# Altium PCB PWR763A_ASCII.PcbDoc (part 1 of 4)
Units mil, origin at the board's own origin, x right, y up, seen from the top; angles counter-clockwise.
Board outline 5000 x 7000 mil, 4 copper layers (Top Layer, Signal Layer 1, Signal Layer 2, Bottom Layer), stack 61.2 mil thick; 559 components, 281 nets, 1477 pads, 685 vias.
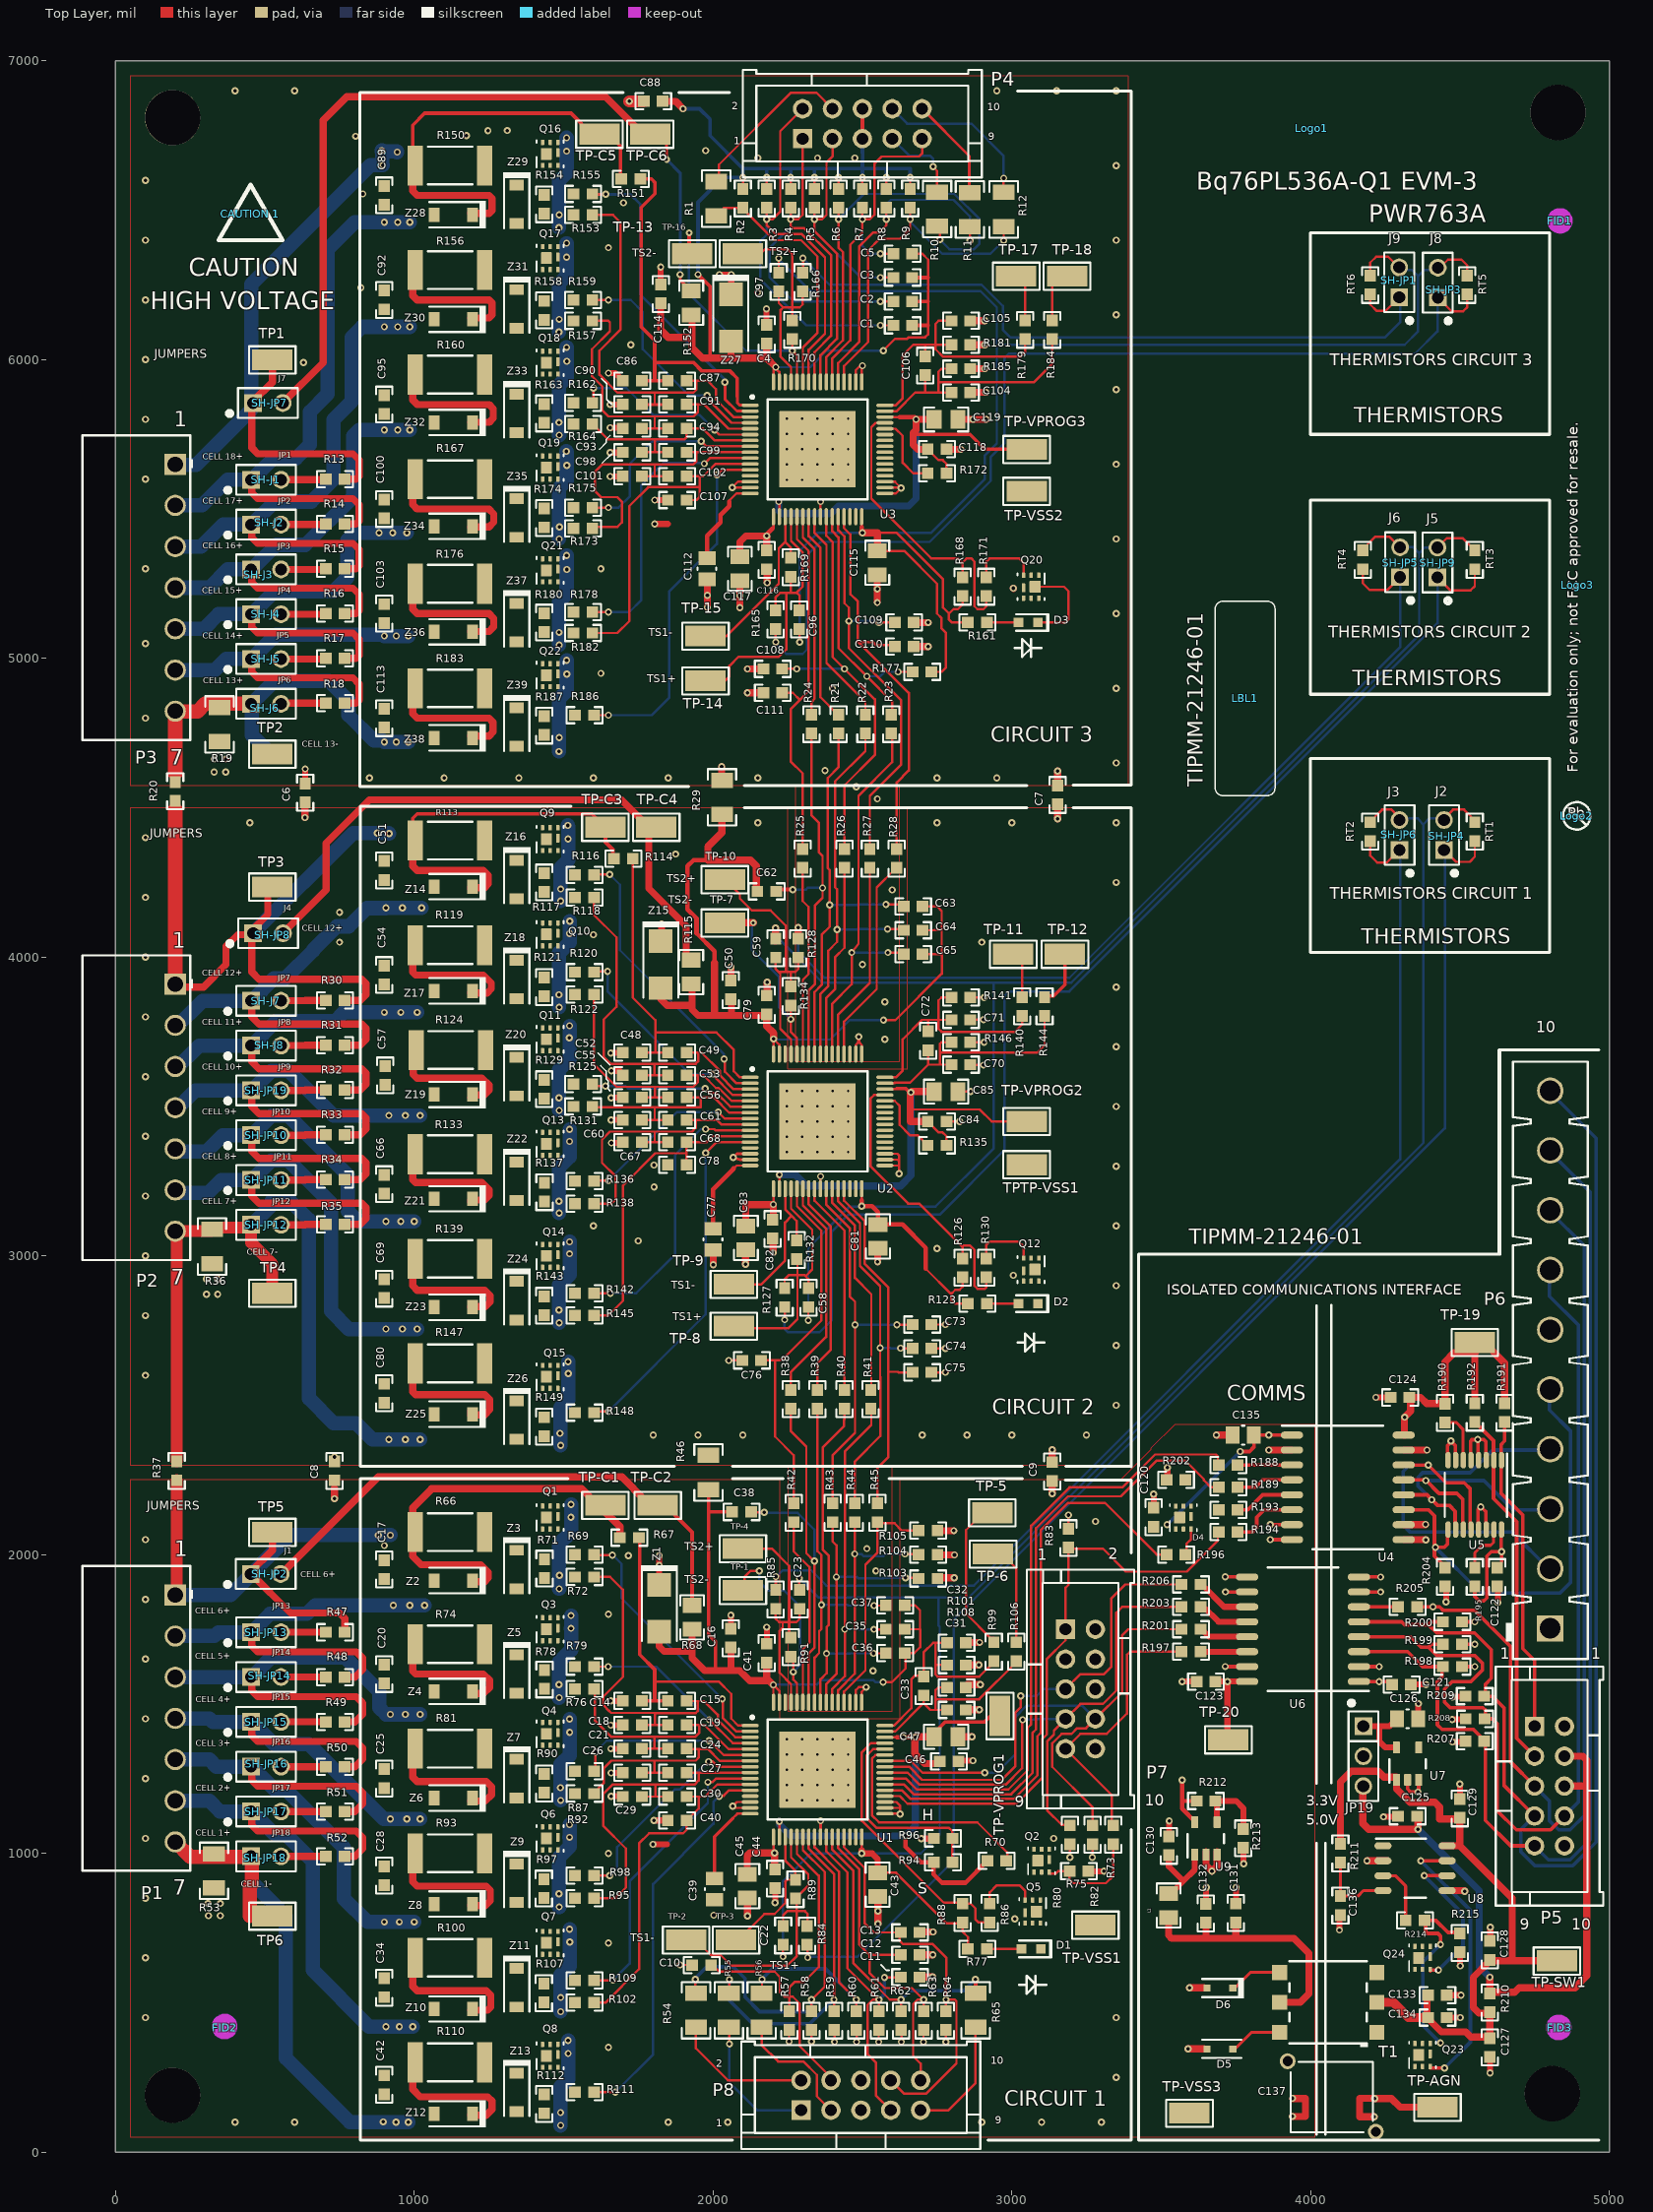
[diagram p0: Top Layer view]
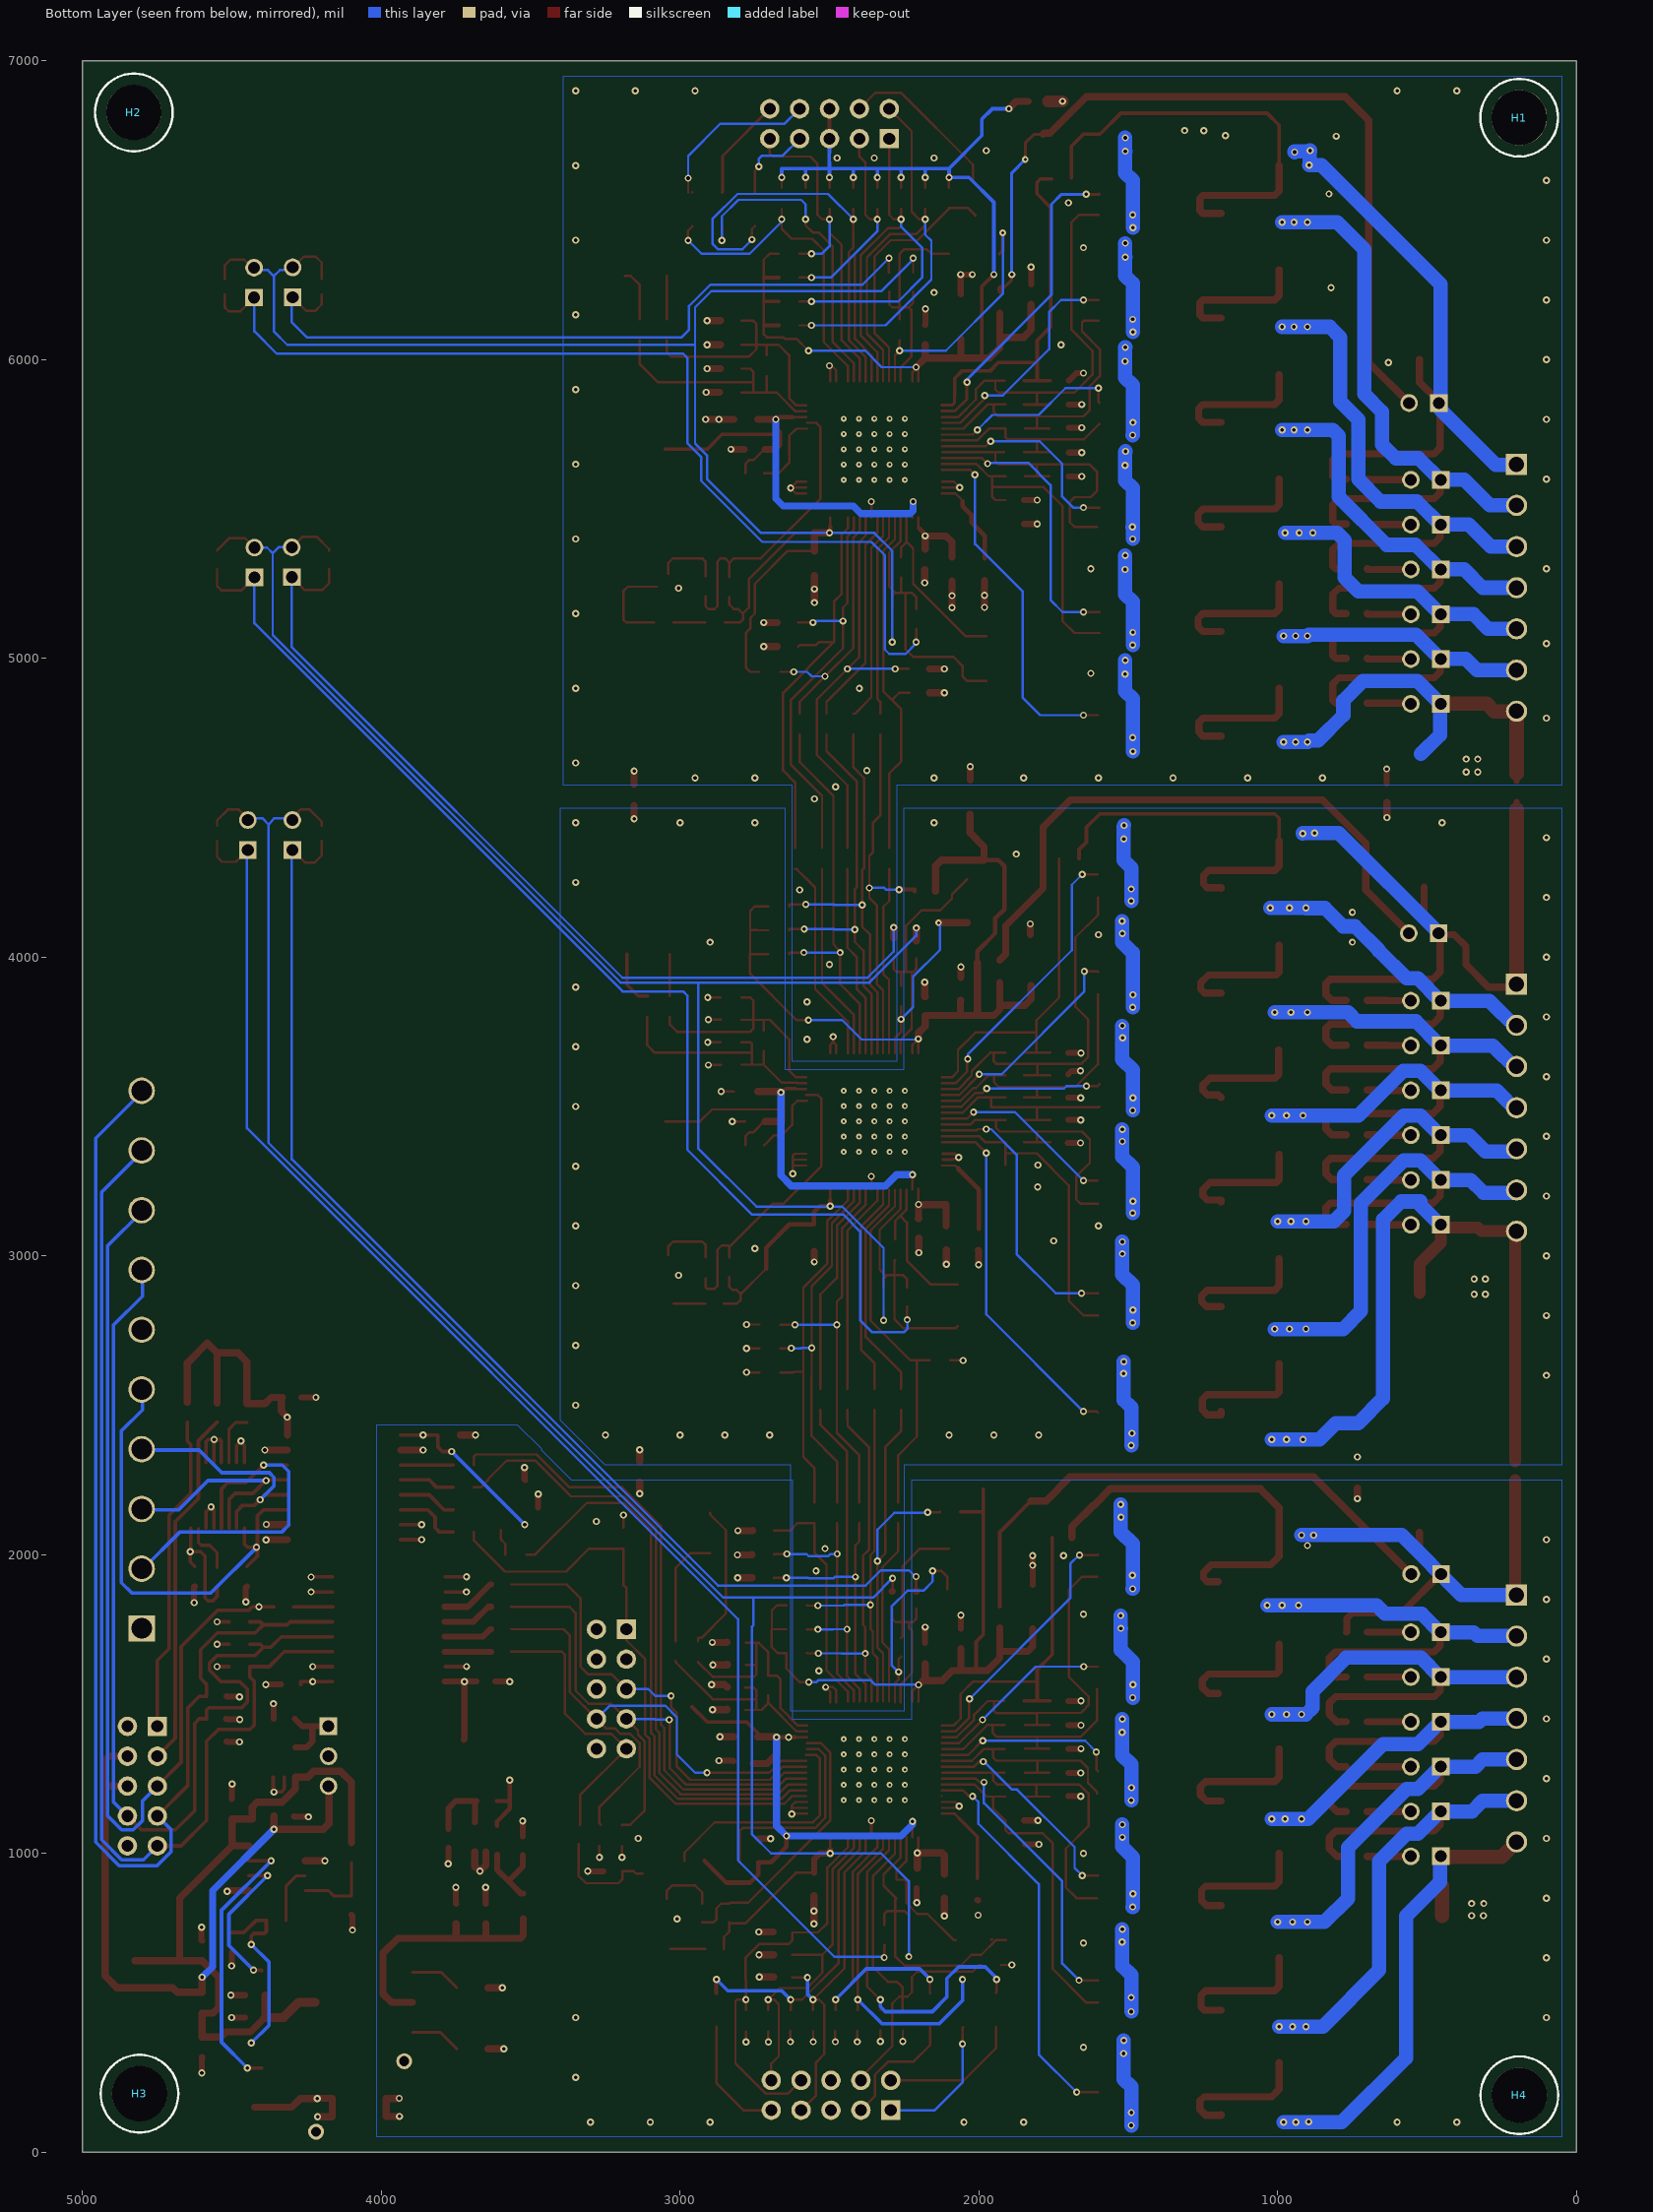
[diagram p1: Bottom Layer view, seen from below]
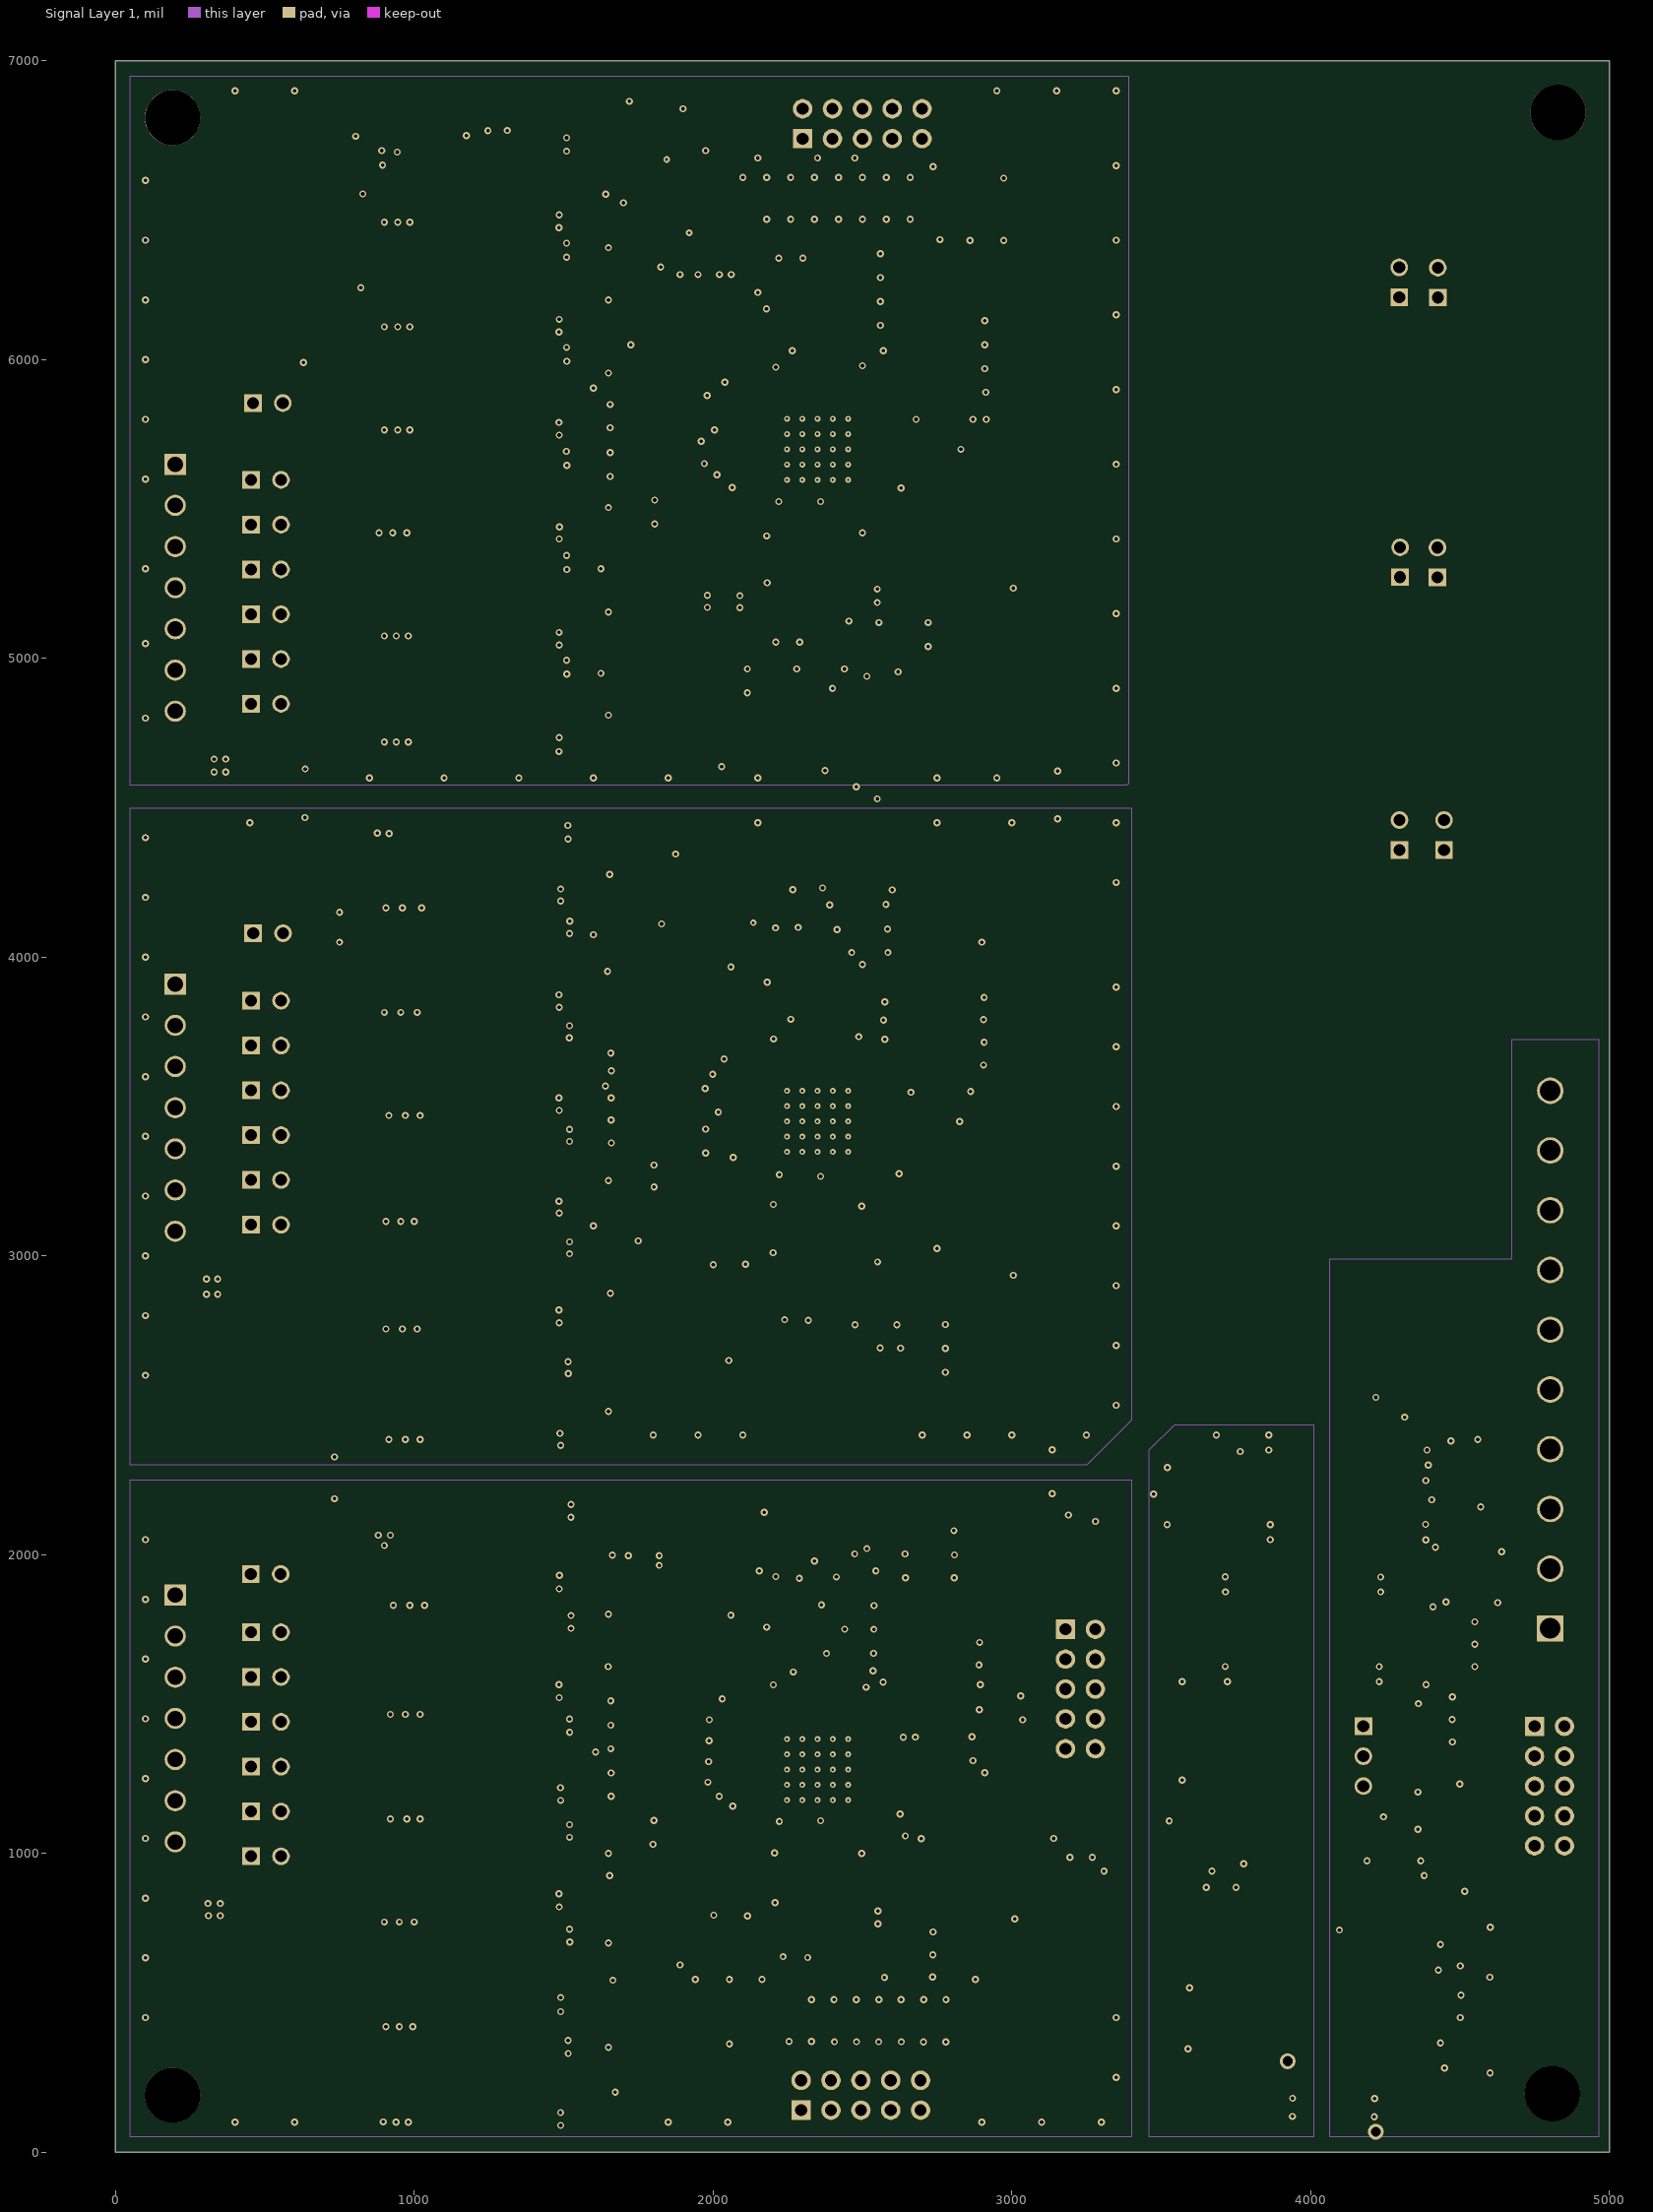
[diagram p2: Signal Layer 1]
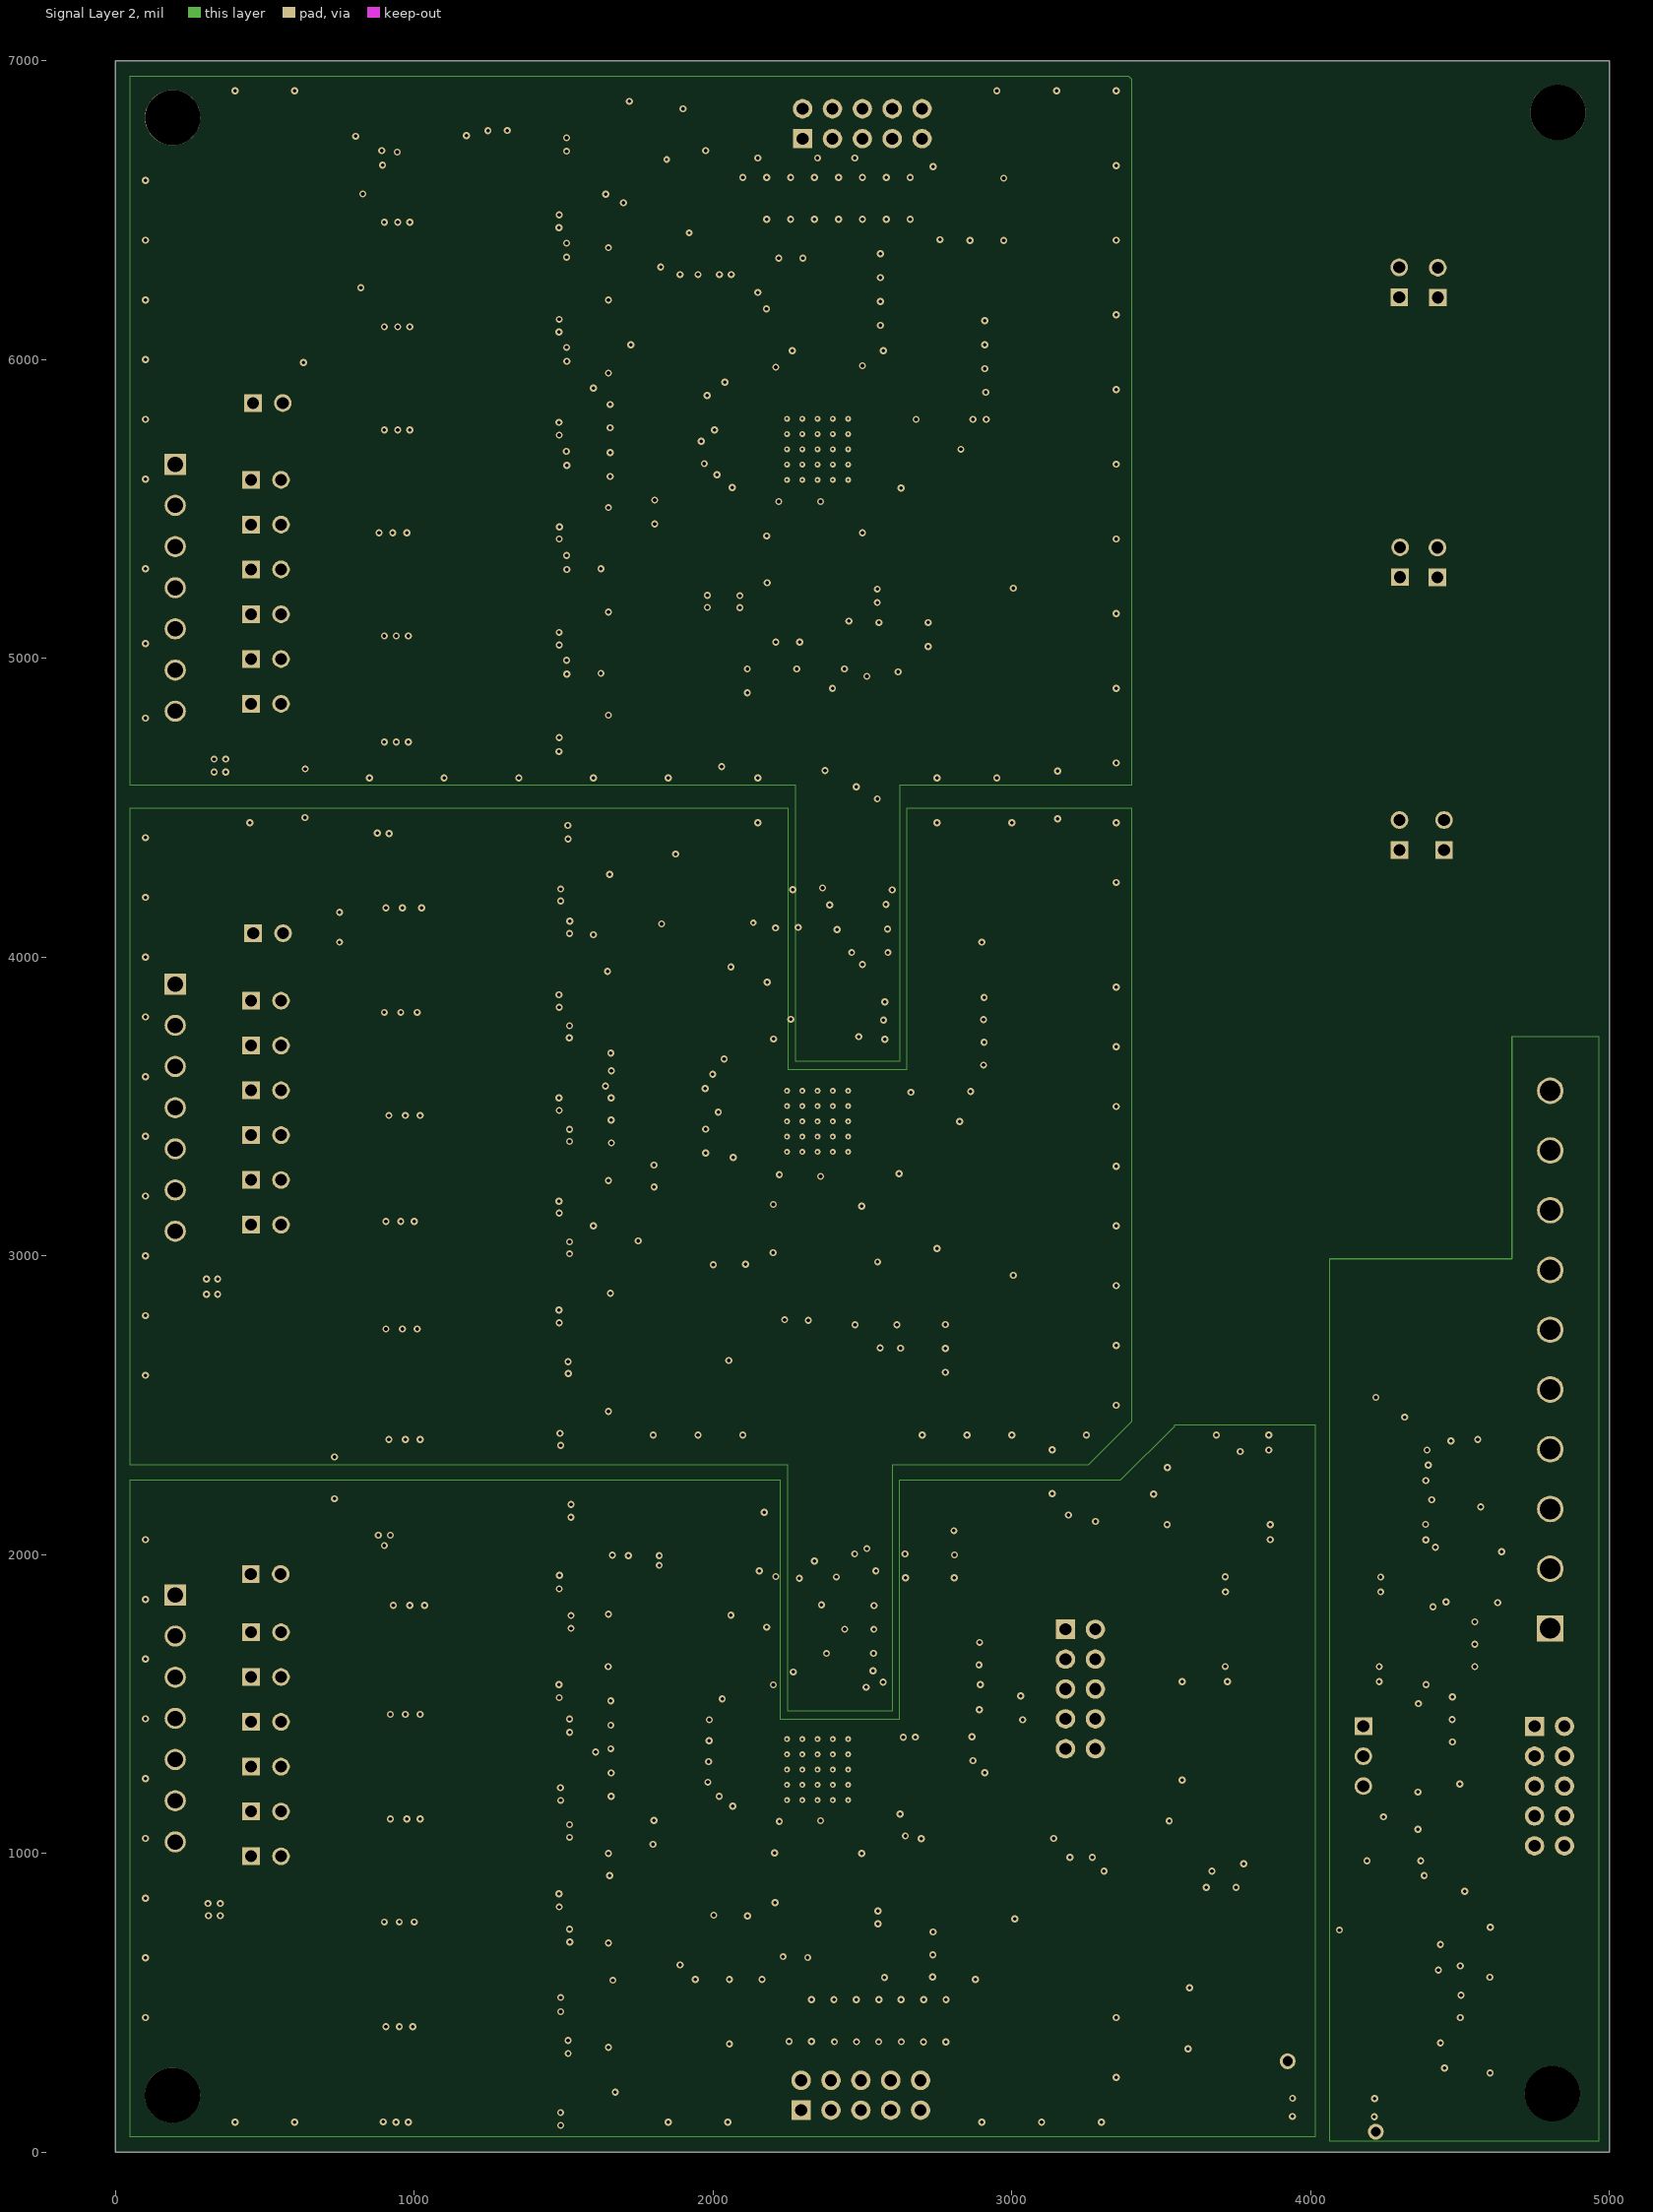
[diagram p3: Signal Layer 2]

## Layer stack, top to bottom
Top Solder: solder mask 0.4, Solder Resist, Dk 3.5
Top Layer: signal copper 2.8
Dielectric1: core 8, FR-4 High Tg, Dk 4.8
Signal Layer 1: signal copper 2.8
Dielectric2: prepreg 32, FR-4 High Tg, Dk 4.8
Signal Layer 2: signal copper 2.8
Dielectric3: core 10, FR-4 High Tg, Dk 4.8
Bottom Layer: signal copper 2.8
Bottom Solder: solder mask 0.4, Solder Resist, Dk 3.5

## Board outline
0,0 5000,0 5000,7000 0,7000

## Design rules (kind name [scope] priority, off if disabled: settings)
AcuteAngle [All] p0: scope1count=1 scope1_0_kind=Board scope1_0_value=Board scope2count=1 scope2_0_kind=Board scope2_0_value=Board commentlength=0 minimum=4.50000000000000E+0001
AcuteAngle [All] p1: minimum=4.50000000000000E+0001 checktracksonly=FALSE
AssemblyTestPointUsage [All] p0: scope1count=1 scope1_0_kind=Board scope1_0_value=Board scope2count=1 scope2_0_kind=Board scope2_0_value=Board commentlength=0
AssemblyTestPointUsage [All] p1: valid=2
AssemblyTestpoint [All] p0: scope1count=1 scope1_0_kind=Board scope1_0_value=Board scope2count=1 scope2_0_kind=Board scope2_0_value=Board commentlength=0
Clearance Clearance_D6 [All] p0: scope1count=1 scope1_0_kind=Component scope1_0_value=D6 scope2count=1 scope2_0_kind=Board scope2_0_value=Board commentlength=0 gap=1
Clearance Clearance_Keepouts [All] p0 off: scope1count=1 scope1_0_kind=Board scope1_0_value=Board scope2count=1 scope2_0_kind=Board scope2_0_value=Board commentlength=99 gap=0 // Protel DXP Scope 2 Expression Was: ((IsTrack Or IsArc) And Not InPoly) And IsFree and IsKeepOut
Clearance Clearance_BoardEdge_MountingHoles [All] p0 off: scope1count=1 scope1_0_kind=Board scope1_0_value=Board scope2count=1 scope2_0_kind=Board scope2_0_value=Board commentlength=48 gap=40 // Protel DXP Scope 2 Expression Was: IsKeepOut
Clearance Clearance_BoardEdge_Poly [All] p0 off: scope1count=1 scope1_0_kind=Board scope1_0_value=Board scope2count=1 scope2_0_kind=Board scope2_0_value=Board commentlength=48 gap=25 // Protel DXP Scope 2 Expression Was: IsKeepOut
Clearance Clearance_BoardEdge [All] p0 off: scope1count=1 scope1_0_kind=Board scope1_0_value=Board scope2count=1 scope2_0_kind=Board scope2_0_value=Board commentlength=48 gap=75 // Protel DXP Scope 2 Expression Was: IsKeepOut
Clearance Clearance_Poly [All] p0 off: scope1count=1 scope1_0_kind=Board scope1_0_value=Board scope2count=1 scope2_0_kind=Board scope2_0_value=Board commentlength=48 gap=25 // Protel DXP Scope 1 Expression Was: InPolygon
Clearance [All] p0: scope1count=1 scope1_0_kind=Board scope1_0_value=Board scope2count=1 scope2_0_kind=Board scope2_0_value=Board commentlength=0 gap=7.87
Clearance Clearance_D6 [InComponent('D6')] p1: gap=1
Clearance Clearance_Keepouts [((IsTrack Or IsArc) And Not InPoly) And IsFree and IsKeepOut vs ((IsTrack Or IsArc) And Not InPoly) And IsFree and IsKeepOut] p2 off: gap=0
Clearance Clearance_BoardEdge_MountingHoles [OnCopper and InComponentClass('Mounting Holes') vs IsKeepOut] p3: gap=40
Clearance Clearance_BoardEdge_Poly [OnCopper and InPoly vs IsKeepOut] p4: gap=25
Clearance Clearance_BoardEdge [OnCopper and Not InComponentClass('Logo') and not InComponentClass('FiducialMark') and not InRegion(1000,500,4000,800) and Not IsKeepout vs IsKeepOut] p5: gap=75
Clearance Clearance_Poly [InPolygon] p6: gap=25
Clearance [All] p7: gap=7.87
ComponentClearance ComponentClearance_MountingHoles_FiducialMarks [All] p0: scope1count=1 scope1_0_kind=ComponentClass scope1_0_value="Mounting Holes" scope2count=1 scope2_0_kind=ComponentClass scope2_0_value=FiducialMark commentlength=0 gap=50 collisioncheckmode=3
ComponentClearance ComponentClearance_Shunt [All] p0: scope1count=1 scope1_0_kind=ComponentClass scope1_0_value=Header scope2count=1 scope2_0_kind=ComponentClass scope2_0_value=Shunt commentlength=0 gap=0 collisioncheckmode=3
ComponentClearance ComponentClearance_Logo [All] p0: scope1count=1 scope1_0_kind=ComponentClass scope1_0_value=Logo scope2count=1 scope2_0_kind=Board scope2_0_value=Board commentlength=0 gap=50 collisioncheckmode=3
ComponentClearance ComponentClearance_ScrewToNut [All] p0 off: scope1count=1 scope1_0_kind=Board scope1_0_value=Board scope2count=1 scope2_0_kind=Board scope2_0_value=Board commentlength=71 gap=5 collisioncheckmode=3 // Protel DXP Scope 2 Expression Was: (HasFootprint('Keystone_1902C'))
ComponentClearance ComponentClearance_MountingHoles [All] p0: scope1count=1 scope1_0_kind=ComponentClass scope1_0_value="Mounting Holes" scope2count=1 scope2_0_kind=Board scope2_0_value=Board commentlength=0 gap=250 collisioncheckmode=3
ComponentClearance ComponentClearance_SmallPassives [All] p0 off: scope1count=1 scope1_0_kind=Board scope1_0_value=Board scope2count=1 scope2_0_kind=Board scope2_0_value=Board commentlength=508 gap=20 collisioncheckmode=3 // Protel DXP Scope 2 Expression Was: HasFootprint('0201*') or HasFootprint('0402*') or HasFootprint('0508') or HasFootprint('0603*') or HasFootprint('0612') or HasFootprint('0805*') or HasFootprint('0815*') or HasFootprint('0830*') or HasFootprint('1206*') or HasFootprint('1210*') or HasFootprint('1808*') or HasFootprint('1812*') or HasFootprint('1825*') or HasFootprint('2010*') or HasFootprint('2220*') or HasFootprint('2225*') or HasFootprint('2512*') or HasFootprint('2728*') or HasFootprint('3518*')
ComponentClearance ComponentClearance_THtoSMT [All] p0 off: scope1count=1 scope1_0_kind=Board scope1_0_value=Board scope2count=1 scope2_0_kind=Board scope2_0_value=Board commentlength=53 gap=8 collisioncheckmode=3 // Protel DXP Scope 2 Expression Was: IsSMTComponent
ComponentClearance ComponentClearance_THtoTH [All] p0 off: scope1count=1 scope1_0_kind=Board scope1_0_value=Board scope2count=1 scope2_0_kind=Board scope2_0_value=Board commentlength=54 gap=20 collisioncheckmode=3 // Protel DXP Scope 2 Expression Was: IsThruComponent
ComponentClearance [All] p0: scope1count=1 scope1_0_kind=Board scope1_0_value=Board scope2count=1 scope2_0_kind=Board scope2_0_value=Board commentlength=0 gap=20 collisioncheckmode=3
ComponentClearance ComponentClearance_MountingHoles_FiducialMarks [InComponentClass('Mounting Holes') vs InComponentClass('FiducialMark')] p1: gap=50 collisioncheckmode=3 verticalgap=10 showdistances=FALSE
ComponentClearance ComponentClearance_Shunt [InComponentClass('Header') vs InComponentClass('Shunt')] p2: gap=0 collisioncheckmode=3 verticalgap=0 showdistances=FALSE
ComponentClearance ComponentClearance_Logo [InComponentClass('Logo')] p3: gap=50 collisioncheckmode=3 verticalgap=10 showdistances=FALSE
ComponentClearance ComponentClearance_ScrewToNut [(HasFootprint('NY PMS 440 0025 PH')) vs (HasFootprint('Keystone_1902C'))] p4: gap=5 collisioncheckmode=3 verticalgap=10 showdistances=FALSE
ComponentClearance ComponentClearance_MountingHoles [InComponentClass('Mounting Holes')] p5: gap=250 collisioncheckmode=3 verticalgap=100000 showdistances=FALSE
ComponentClearance ComponentClearance_SmallPassives [HasFootprint('0201*') or HasFootprint('0402*') or HasFootprint('0508') or HasFootprint('0603*') or HasFootprint('0612') or HasFootprint('0805*') or HasFootprint('0815*') or HasFootprint('0830*') or HasFootprint('1206*') or HasFootprint('1210*') or HasFootprint('1808*') or HasFootprint('1812*') or HasFootprint('1825*') or HasFootprint('2010*') or HasFootprint('2220*') or HasFootprint('2225*') or HasFootprint('2512*') or HasFootprint('2728*') or HasFootprint('3518*') vs HasFootprint('0201*') or HasFootprint('0402*') or HasFootprint('0508') or HasFootprint('0603*') or HasFootprint('0612') or HasFootprint('0805*') or HasFootprint('0815*') or HasFootprint('0830*') or HasFootprint('1206*') or HasFootprint('1210*') or HasFootprint('1808*') or HasFootprint('1812*') or HasFootprint('1825*') or HasFootprint('2010*') or HasFootprint('2220*') or HasFootprint('2225*') or HasFootprint('2512*') or HasFootprint('2728*') or HasFootprint('3518*')] p6: gap=20 collisioncheckmode=3 verticalgap=10 showdistances=FALSE
ComponentClearance ComponentClearance_THtoSMT [IsThruComponent vs IsSMTComponent] p7: gap=8 collisioncheckmode=3 verticalgap=30 showdistances=FALSE
ComponentClearance ComponentClearance_THtoTH [IsThruComponent vs IsThruComponent] p8: gap=20 collisioncheckmode=3 verticalgap=30 showdistances=FALSE
ComponentClearance [All] p9: gap=20 collisioncheckmode=3 verticalgap=10 showdistances=FALSE
DiffPairsRouting [All] p0: scope1count=1 scope1_0_kind=Board scope1_0_value=Board scope2count=1 scope2_0_kind=Board scope2_0_value=Board commentlength=0
DiffPairsRouting [All] p1: maxlimit=100 minlimit=10 mostfreqgap=10 toplayer_minwidth=15 toplayer_maxwidth=15 toplayer_prefwidth=15 midlayer1_minwidth=15 midlayer1_maxwidth=15 midlayer1_prefwidth=15 midlayer2_minwidth=15 midlayer2_maxwidth=15 midlayer2_prefwidth=15 bottomlayer_minwidth=15 bottomlayer_maxwidth=15 bottomlayer_prefwidth=15 maxuncoupledlength=1000
FabricationTestPointUsage TestPointUsage [All] p0: scope1count=1 scope1_0_kind=Board scope1_0_value=Board scope2count=1 scope2_0_kind=Board scope2_0_value=Board commentlength=0 valid=2 allowmultiple=FALSE
FabricationTestPointUsage TestPointUsage [All] p1: valid=2 allowmultiple=FALSE
FabricationTestpoint Testpoint [All] p0: scope1count=1 scope1_0_kind=Board scope1_0_value=Board scope2count=1 scope2_0_kind=Board scope2_0_value=Board commentlength=0 side=3 testpointundercomponent=TRUE minsize=40 maxsize=100 preferedsize=60 minholesize=0 maxholesize=40 preferedholesize=32 testpointgrid=1
FabricationTestpoint Testpoint [All] p1: side=3 testpointundercomponent=TRUE minsize=40 maxsize=100 preferedsize=60 minholesize=0 maxholesize=40 preferedholesize=32 testpointgrid=1 allowsidetop=TRUE allowsidebottom=TRUE usegrid=TRUE gridtolerance=0.01
FanoutControl Fanout_LCC [All] p0 off: scope1count=1 scope1_0_kind=Board scope1_0_value=Board scope2count=1 scope2_0_kind=Board scope2_0_value=Board commentlength=69 // Protel DXP Scope 1 Expression Was: IsLCC   Fanout_LCC (Default Rule)
FanoutControl Fanout_BGA [All] p0 off: scope1count=1 scope1_0_kind=Board scope1_0_value=Board scope2count=1 scope2_0_kind=Board scope2_0_value=Board commentlength=69 // Protel DXP Scope 1 Expression Was: IsBGA   Fanout_BGA (Default Rule)
FanoutControl Fanout_SOIC [All] p0 off: scope1count=1 scope1_0_kind=Board scope1_0_value=Board scope2count=1 scope2_0_kind=Board scope2_0_value=Board commentlength=71 // Protel DXP Scope 1 Expression Was: IsSOIC   Fanout_SOIC (Default Rule)
FanoutControl Fanout_Default [All] p0: scope1count=1 scope1_0_kind=Board scope1_0_value=Board scope2count=1 scope2_0_kind=Board scope2_0_value=Board commentlength=30 // Fanout_Default (Default Rule)
FanoutControl Fanout_Small [All] p0 off: scope1count=1 scope1_0_kind=Board scope1_0_value=Board scope2count=1 scope2_0_kind=Board scope2_0_value=Board commentlength=84 // Protel DXP Scope 1 Expression Was: (CompPinCount < 5)   Fanout_Small (Default Rule)
FanoutControl Fanout_LCC [IsLCC] p1: bgadir=Out bgaviamode=Centered fanoutstyle=Auto fanoutdirection=Alternating viagrid=1 // Fanout_LCC (Default Rule)
FanoutControl Fanout_BGA [IsBGA] p2: bgadir=Out bgaviamode=Centered fanoutstyle=Auto fanoutdirection=Alternating viagrid=1 // Fanout_BGA (Default Rule)
FanoutControl Fanout_Default [All] p4: bgadir=Out bgaviamode=Centered fanoutstyle=Auto fanoutdirection=Alternating viagrid=1 // Fanout_Default (Default Rule)
FanoutControl Fanout_Small [(CompPinCount < 5)] p5: bgadir=Out bgaviamode=Centered fanoutstyle=Auto fanoutdirection=OutThenIn viagrid=1 // Fanout_Small (Default Rule)
Height [All] p0: scope1count=1 scope1_0_kind=Board scope1_0_value=Board scope2count=1 scope2_0_kind=Board scope2_0_value=Board commentlength=0
HoleSize [All] p0: scope1count=1 scope1_0_kind=Board scope1_0_value=Board scope2count=1 scope2_0_kind=Board scope2_0_value=Board commentlength=0 absolutevalues=TRUE maxlimit=251 minlimit=7.87 maxpercent=80.000 minpercent=20.000
HoleSize [All] p1: absolutevalues=TRUE maxlimit=251 minlimit=7.87 maxpercent=80.000 minpercent=20.000
HoleToHoleClearance [All] p0: scope1count=1 scope1_0_kind=Board scope1_0_value=Board scope2count=1 scope2_0_kind=Board scope2_0_value=Board commentlength=0
LayerPairs [All] p0: scope1count=1 scope1_0_kind=Board scope1_0_value=Board scope2count=1 scope2_0_kind=Board scope2_0_value=Board commentlength=0 enforce=TRUE
MinimumAnnularRing MinimumAnnularRing_ThermalPadVias [All] p0 off: scope1count=1 scope1_0_kind=Board scope1_0_value=Board scope2count=1 scope2_0_kind=Board scope2_0_value=Board commentlength=63 minimumring=5.91 // Protel DXP Scope 1 Expression Was: IsVia and InAnyComponent
MinimumAnnularRing [All] p0: scope1count=1 scope1_0_kind=Board scope1_0_value=Board scope2count=1 scope2_0_kind=Board scope2_0_value=Board commentlength=0 minimumring=6
MinimumAnnularRing MinimumAnnularRing_ThermalPadVias [IsVia and InAnyComponent] p1: minimumring=5.91
MinimumAnnularRing [All] p2: minimumring=6
MinimumSolderMaskSliver MinimumSolderMaskSliver_U6 [All] p0: scope1count=1 scope1_0_kind=Component scope1_0_value=D6 scope2count=1 scope2_0_kind=Board scope2_0_value=Board commentlength=0
MinimumSolderMaskSliver MinimumSolderMaskSliver_Logo [All] p0: scope1count=1 scope1_0_kind=ComponentClass scope1_0_value=Logo scope2count=1 scope2_0_kind=ComponentClass scope2_0_value=Logo commentlength=0
MinimumSolderMaskSliver [All] p0: scope1count=1 scope1_0_kind=Board scope1_0_value=Board scope2count=1 scope2_0_kind=Board scope2_0_value=Board commentlength=0
MinimumSolderMaskSliver MinimumSolderMaskSliver_U6 [InComponent('D6')] p1: minsoldermaskwidth=1
MinimumSolderMaskSliver MinimumSolderMaskSliver_Logo [InComponentClass('Logo') vs InComponentClass('Logo')] p2: minsoldermaskwidth=0.7
MinimumSolderMaskSliver [All] p3: minsoldermaskwidth=3.93
NetAntennae [All] p0: scope1count=1 scope1_0_kind=Board scope1_0_value=Board scope2count=1 scope2_0_kind=Board scope2_0_value=Board commentlength=0
PasteMaskExpansion [All] p0: scope1count=1 scope1_0_kind=Board scope1_0_value=Board scope2count=1 scope2_0_kind=Board scope2_0_value=Board commentlength=0 expansion=0
PlaneClearance [All] p0: scope1count=1 scope1_0_kind=Board scope1_0_value=Board scope2count=1 scope2_0_kind=Board scope2_0_value=Board commentlength=0 clearance=20
PlaneConnect [All] p0: scope1count=1 scope1_0_kind=Board scope1_0_value=Board scope2count=1 scope2_0_kind=Board scope2_0_value=Board commentlength=0 planeconnectstyle=Direct reliefexpansion=10 reliefentries=4 reliefconductorwidth=10 reliefairgap=10
PlaneConnect [All] p1: planeconnectstyle=Direct reliefexpansion=10 reliefentries=4 reliefconductorwidth=10 reliefairgap=10
PolygonConnect [All] p0: scope1count=1 scope1_0_kind=Board scope1_0_value=Board scope2count=1 scope2_0_kind=Board scope2_0_value=Board commentlength=0 connectstyle=Direct reliefconductorwidth=10 reliefentries=4 polygonreliefangle="90 Angle"
PolygonConnect [All] p1: connectstyle=Direct reliefconductorwidth=10 reliefentries=4 polygonreliefangle="90 Angle" airgapwidth=10
RoutingCorners [All] p0: scope1count=1 scope1_0_kind=Board scope1_0_value=Board scope2count=1 scope2_0_kind=Board scope2_0_value=Board commentlength=0 cornerstyle=45-Degree minsetback=100 maxsetback=100
RoutingLayers [All] p0: scope1count=1 scope1_0_kind=Board scope1_0_value=Board scope2count=1 scope2_0_kind=Board scope2_0_value=Board commentlength=0 top layer=Automatic mid layer 1=Automatic mid layer 2=Automatic bottom layer=Automatic
RoutingPriority [All] p0: scope1count=1 scope1_0_kind=Board scope1_0_value=Board scope2count=1 scope2_0_kind=Board scope2_0_value=Board commentlength=0
RoutingTopology [All] p0: scope1count=1 scope1_0_kind=Board scope1_0_value=Board scope2count=1 scope2_0_kind=Board scope2_0_value=Board commentlength=0 topology=Shortest
RoutingVias ThermalPadVias [All] p0 off: scope1count=1 scope1_0_kind=Board scope1_0_value=Board scope2count=1 scope2_0_kind=Board scope2_0_value=Board commentlength=63 holewidth=7.87 width=19.68 viastyle="Through Hole" minholewidth=7.87 minwidth=19.68 maxholewidth=12.99 maxwidth=23.62 // Protel DXP Scope 1 Expression Was: IsVia and InAnyComponent
RoutingVias [All] p0: scope1count=1 scope1_0_kind=Board scope1_0_value=Board scope2count=1 scope2_0_kind=Board scope2_0_value=Board commentlength=0 holewidth=16 width=34 viastyle="Through Hole" minholewidth=7.87 minwidth=22 maxholewidth=40 maxwidth=65
RoutingVias ThermalPadVias [IsVia and InAnyComponent] p1: holewidth=7.87 width=19.68 viastyle="Through Hole" minholewidth=7.87 minwidth=19.68 maxholewidth=12.99 maxwidth=23.62
RoutingVias [All] p2: holewidth=16 width=34 viastyle="Through Hole" minholewidth=7.87 minwidth=22 maxholewidth=40 maxwidth=65
ShortCircuit [All] p0: scope1count=1 scope1_0_kind=Board scope1_0_value=Board scope2count=1 scope2_0_kind=Board scope2_0_value=Board commentlength=0 allowed=FALSE
SilkToBoardRegionClearance [All] p0 off: scope1count=1 scope1_0_kind=Board scope1_0_value=Board scope2count=1 scope2_0_kind=Board scope2_0_value=Board commentlength=130 // Protel DXP Scope 1 Expression Was: Not ((IsComment or IsDesignator) And (Hide <> 'False')) and not InRegion(1000,500,4000,800)
SilkToBoardRegionClearance [Not ((IsComment or IsDesignator) And (Hide <> 'False')) and not InRegion(1000,500,4000,800)] p1:
SilkToSilkClearance SilkToSilkClearance_Pb-FreeLogo [All] p0 off: scope1count=1 scope1_0_kind=Board scope1_0_value=Board scope2count=1 scope2_0_kind=Board scope2_0_value=Board commentlength=120 // Protel DXP Scope 2 Expression Was: (HasFootprint('Pb-Free_Overlay_Medium') OR HasFootprint('Pb-Free_Overlay_Small'))
SilkToSilkClearance [All] p0: scope1count=1 scope1_0_kind=Board scope1_0_value=Board scope2count=1 scope2_0_kind=Board scope2_0_value=Board commentlength=0
SilkToSilkClearance SilkToSilkClearance_Pb-FreeLogo [(HasFootprint('Pb-Free_Overlay_Medium') OR HasFootprint('Pb-Free_Overlay_Small')) vs (HasFootprint('Pb-Free_Overlay_Medium') OR HasFootprint('Pb-Free_Overlay_Small'))] p1: silktosilkclearance=0
SilkToSilkClearance [All] p2: silktosilkclearance=5
SilkToSolderMaskClearance [All] p0 off: scope1count=1 scope1_0_kind=Board scope1_0_value=Board scope2count=1 scope2_0_kind=Board scope2_0_value=Board commentlength=44 // Protel DXP Scope 1 Expression Was: IsPad
SilkToSolderMaskClearance "Silk to Solder Mask fp_1" [All] p0 off: scope1count=1 scope1_0_kind=Board scope1_0_value=Board scope2count=1 scope2_0_kind=Board scope2_0_value=Board commentlength=151 // Protel DXP Scope 1 Expression Was: (HasFootprint('CAPRD750W60D700H1000') OR HasFootprint('Samtec_HPM-10-05-T-S')OR HasFootprint('Molex_395021007'))
SilkToSolderMaskClearance "Silk to Solder Mask fp_1" [(HasFootprint('CAPRD750W60D700H1000') OR HasFootprint('Samtec_HPM-10-05-T-S')OR HasFootprint('Molex_395021007'))] p1: minsilkscreentomaskgap=0 clearancetoexposedcopper=FALSE
SilkToSolderMaskClearance [IsPad] p2: minsilkscreentomaskgap=3 clearancetoexposedcopper=TRUE
SolderMaskExpansion [All] p0: scope1count=1 scope1_0_kind=Board scope1_0_value=Board scope2count=1 scope2_0_kind=Board scope2_0_value=Board commentlength=0 expansion=1.97
SolderMaskExpansion [All] p1: expansion=1.97
UnRoutedNet [All] p0: scope1count=1 scope1_0_kind=Board scope1_0_value=Board scope2count=1 scope2_0_kind=Board scope2_0_value=Board commentlength=0
UnpouredPolygon [All] p0: scope1count=1 scope1_0_kind=Board scope1_0_value=Board scope2count=1 scope2_0_kind=Board scope2_0_value=Board commentlength=0
UnpouredPolygon [All] p1: allowunpoured=FALSE
Width [All] p0: scope1count=1 scope1_0_kind=Board scope1_0_value=Board scope2count=1 scope2_0_kind=Board scope2_0_value=Board commentlength=0 maxlimit=100 minlimit=6 preferedwidth=10
Width [All] p1: maxlimit=100 minlimit=6 preferedwidth=10 checkconnectedcopper=TRUE
14 further rules are at their usual default settings.

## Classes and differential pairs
component class Logo: Logo1
component class PWR763A_Hardware: "CAUTION 1" FID1 FID2 FID3 H1 H2 H3 H4 LBL1 Logo1 Logo2 Logo3 SH-J1 SH-J2 SH-J3 SH-J4 SH-J5 SH-J6 SH-J7 SH-J8 SH-JP1 SH-JP2 SH-JP3 SH-JP4 SH-JP5 SH-JP6 SH-JP7 SH-JP8 SH-JP9 SH-JP10 SH-JP11 SH-JP12 SH-JP13 SH-JP14 SH-JP15 SH-JP16 SH-JP17 SH-JP18 SH-JP19 ZZ1 ZZ2 ZZ3 ZZ4 ZZ5
component class FiducialMark: FID1 FID2 FID3
component class AssemblyNote: ZZ1 ZZ2 ZZ3 ZZ4 ZZ5
component class Label: LBL1
component class Header: J1 J2 J3 J4 J5 J6 J7 J8 J9 JP1 JP2 JP3 JP4 JP5 JP6 JP7 JP8 JP9 JP10 JP11 JP12 JP13 JP14 JP15 JP16 JP17 JP18 JP19 P6
component class PWR763A_1: C1 C2 C3 C4 C5 C6 C7 C8 C9 C10 C11 C12 C13 JP1 JP2 JP3 JP4 JP5 JP6 JP7 JP8 JP9 JP10 JP11 JP12 JP13 JP14 JP15 JP16 JP17 JP18 P1 P2 P3 P4 P5 P6 P7 P8 R1 R2 R3 R4 R5 R6 R7 R8 R9 R10 R11 R12 R13 R14 R15 R16 R17 R18 R19 R20 R21 R22 R23 R24 R25 R26 R27 R28 R29 R30 R31 R32 R33 R34 R35 R36 R37 R38 R39 R40 R41 R42 R43 R44 R45 R46 R47 R48 R49 R50 R51 R52 R53 R54 R55 R56 R57 R58 R59 R60 R61 R62 R63 R64 R65 TP1 TP2 TP3 TP4 TP5 TP6
component class PWR763A_2: C14 C15 C16 C17 C18 C19 C20 C21 C22 C23 C24 C25 C26 C27 C28 C29 C30 C31 C32 C33 C34 C35 C36 C37 C38 C39 C40 C41 C42 C43 C44 C45 C46 C47 D1 J1 J2 J3 Q1 Q2 Q3 Q4 Q5 Q6 Q7 Q8 R66 R67 R68 R69 R70 R71 R72 R73 R74 R75 R76 R77 R78 R79 R80 R81 R82 R83 R84 R85 R86 R87 R88 R89 R90 R91 R92 R93 R94 R95 R96 R97 R98 R99 R100 R101 R102 R103 R104 R105 R106 R107 R108 R109 R110 R111 R112 RT1 RT2 TP-1 TP-2 TP-3 TP-4 TP-5 TP-6 TP-C1 TP-C2 TP-VPROG1 TP-VSS1 U1 Z1 Z2 Z3 Z4 Z5 Z6 Z7 Z8 Z9 Z10 Z11 Z12 Z13
component class PWR763A_3: C48 C49 C50 C51 C52 C53 C54 C55 C56 C57 C58 C59 C60 C61 C62 C63 C64 C65 C66 C67 C68 C69 C70 C71 C72 C73 C74 C75 C76 C77 C78 C79 C80 C81 C82 C83 C84 C85 D2 J4 J5 J6 Q9 Q10 Q11 Q12 Q13 Q14 Q15 R113 R114 R115 R116 R117 R118 R119 R120 R121 R122 R123 R124 R125 R126 R127 R128 R129 R130 R131 R132 R133 R134 R135 R136 R137 R138 R139 R140 R141 R142 R143 R144 R145 R146 R147 R148 R149 RT3 RT4 TP-7 TP-8 TP-9 TP-10 TP-11 TP-12 TP-C3 TP-C4 TP-VPROG2 TPTP-VSS1 U2 Z14 Z15 Z16 Z17 Z18 Z19 Z20 Z21 Z22 Z23 Z24 Z25 Z26
component class PWR763A_4: C86 C87 C88 C89 C90 C91 C92 C93 C94 C95 C96 C97 C98 C99 C100 C101 C102 C103 C104 C105 C106 C107 C108 C109 C110 C111 C112 C113 C114 C115 C116 C117 C118 C119 D3 J7 J8 J9 Q16 Q17 Q18 Q19 Q20 Q21 Q22 R150 R151 R152 R153 R154 R155 R156 R157 R158 R159 R160 R161 R162 R163 R164 R165 R166 R167 R168 R169 R170 R171 R172 R173 R174 R175 R176 R177 R178 R179 R180 R181 R182 R183 R184 R185 R186 R187 RT5 RT6 TP-13 TP-14 TP-15 TP-16 TP-17 TP-18 TP-C5 TP-C6 TP-VPROG3 TP-VSS2 U3 Z27 Z28 Z29 Z30 Z31 Z32 Z33 Z34 Z35 Z36 Z37 Z38 Z39
component class PWR763A_5: C120 C121 C122 C123 C124 C125 C126 C127 C128 C129 C130 C131 C132 C133 C134 C135 C136 C137 D4 D5 D6 JP19 L1 Q23 Q24 R188 R189 R190 R191 R192 R193 R194 R195 R196 R197 R198 R199 R200 R201 R202 R203 R204 R205 R206 R207 R208 R209 R210 R211 R212 R213 R214 R215 T1 TP-19 TP-20 TP-AGN TP-SW1 TP-VSS3 U4 U5 U6 U7 U8 U9
component class Shunt: SH-J1 SH-J2 SH-J3 SH-J4 SH-J5 SH-J6 SH-J7 SH-J8 SH-JP1 SH-JP2 SH-JP3 SH-JP4 SH-JP5 SH-JP6 SH-JP7 SH-JP8 SH-JP9 SH-JP10 SH-JP11 SH-JP12 SH-JP13 SH-JP14 SH-JP15 SH-JP16 SH-JP17 SH-JP18 SH-JP19

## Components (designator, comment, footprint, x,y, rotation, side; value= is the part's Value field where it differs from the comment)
C1 "06035C104KAT2A" 0603#1 2635,6115 r180 top
C2 "06035C104KAT2A" 0603#1 2635,6195 r180 top
C3 "06035C104KAT2A" 0603#1 2635,6275 r180 top
C4 "06035C104KAT2A" 0603#1 2180,6085 r90 top
C5 "06035C104KAT2A" 0603#1 2635,6355 r180 top
C6 "GRM188R71H332KA01D" 0603#1 635,4550 r90 top
C7 "GRM188R71H332KA01D" 0603#1 3154,4543 r270 top
C8 "GRM188R71H332KA01D" 0603#1 733,2280 r90 top
C9 "GRM188R71H332KA01D" 0603#1 3135,2278 r270 top
C10 "06035C104KAT2A" 0603#1 1962,626 r180 top
C11 "06035C104KAT2A" 0603#1 2660,585 r0 top
C12 "06035C104KAT2A" 0603#1 2660,660 r0 top
C13 "06035C104KAT2A" 0603#1 2660,735 r0 top
C14 "06035C104KAT2A" 0603#1 1730,1510 r180 top
C15 "GRM188R72A104KA35D" 0603#1 1880,1510 r0 top
C16 "GRM188R72A104KA35D" 0603#1 2060,1720 r90 top
C17 "06035C104KAT2A" 0603#1 900,1950 r270 top
C18 "06035C104KAT2A" 0603#1 1730,1430 r180 top
C19 "GRM188R72A104KA35D" 0603#1 1880,1430 r0 top
C20 "06035C104KAT2A" 0603#1 900,1600 r270 top
C21 "06035C104KAT2A" 0603#1 1730,1350 r180 top
C22 "GRM188R71C473KA01D" 0603#1 2235,725 r90 top
C23 "GRM188R71C473KA01D" 0603#1 2290,1850 r270 top
C24 "GRM188R72A104KA35D" 0603#1 1880,1350 r0 top
C25 "06035C104KAT2A" 0603#1 900,1250 r270 top
C26 "06035C104KAT2A" 0603#1 1730,1270 r180 top
C27 "GRM188R72A104KA35D" 0603#1 1880,1270 r0 top
C28 "06035C104KAT2A" 0603#1 900,925 r270 top
C29 "06035C104KAT2A" 0603#1 1730,1190 r180 top
C30 "GRM188R72A104KA35D" 0603#1 1880,1190 r0 top
C31 "C0603C104K4RACTU" 0603#1 2815,1480 r0 top
C32 "C0603C104K4RACTU" 0603#1 2815,1705 r0 top
C33 "C0603C104K4RACTU" 0603#1 2705,1560 r270 top
C34 "GRM188R72A104KA35D" 0603#1 900,550 r270 top
C35 "GRM1885C1H330JA01D" 0603#1 2610,1750 r0 top
C36 "GRM1885C1H330JA01D" 0603#1 2610,1670 r0 top
C37 "GRM1885C1H330JA01D" 0603#1 2610,1830 r0 top
C38 "GRM1885C1H330JA01D" 0603#1 2095.67,2142.55 r180 top
C39 "C2012X7R1A106M125AC" 0805_145 2005,880 r270 top
C40 "06035C104KAT2A" 0603#1 1880,1110 r180 top
C41 "06035C104KAT2A" 0603#1 2180,1670 r90 top
C42 "06035C104KAT2A" 0603#1 900,225 r270 top
C43 "GRM21BR71A225KA01L" 0805_HV 2551,895 r270 top
C44 "06035C104KAT2A" 0603#1 2208,915 r270 top
C45 "GRM21BR71A225KA01L" 0805_HV 2115,890 r270 top
C46 "06035C104KAT2A" 0603#1 2790,1308 r0 top
C47 "GRM21BR71A225KA01L" 0805_HV 2780,1390 r0 top
C48 "06035C104KAT2A" 0603#1 1730,3680 r180 top
C49 "GRM188R72A104KA35D" 0603#1 1880,3680 r0 top
C50 "GRM188R72A104KA35D" 0603#1 2060,3890 r90 top
C51 "06035C104KAT2A" 0603#1 900,4290 r270 top
C52 "06035C104KAT2A" 0603#1 1730,3605 r180 top
C53 "GRM188R72A104KA35D" 0603#1 1880,3605 r0 top
C54 "06035C104KAT2A" 0603#1 900,3940 r270 top
C55 "06035C104KAT2A" 0603#1 1730,3530 r180 top
C56 "GRM188R72A104KA35D" 0603#1 1880,3530 r0 top
C57 "06035C104KAT2A" 0603#2 711,3524 r270 top
C58 "GRM188R71C473KA01D" 0603#1 2320,2860 r90 top
C59 "GRM188R71C473KA01D" 0603#1 2210,4030 r270 top
C60 "06035C104KAT2A" 0603#1 1730,3455 r180 top
C61 "GRM188R72A104KA35D" 0603#1 1880,3455 r0 top
C62 "GRM1885C1H330JA01D" 0603#1 2180,4220 r0 top
C63 "GRM1885C1H330JA01D" 0603#1 2670,4170 r180 top
C64 "GRM1885C1H330JA01D" 0603#1 2670,4090 r180 top
C65 "GRM1885C1H330JA01D" 0603#1 2670,4010 r180 top
C66 "06035C104KAT2A" 0603#1 900,3240 r270 top
C67 "06035C104KAT2A" 0603#1 1730,3380 r180 top
C68 "GRM188R72A104KA35D" 0603#1 1880,3380 r0 top
C69 "GRM188R72A104KA35D" 0603#1 900,2890 r270 top
C70 "C0603C104K4RACTU" 0603#1 2830,3640 r0 top
C71 "C0603C104K4RACTU" 0603#1 2830,3790 r0 top
C72 "C0603C104K4RACTU" 0603#1 2720,3720 r270 top
C73 "GRM1885C1H330JA01D" 0603#1 2700,2770 r0 top
C74 "GRM1885C1H330JA01D" 0603#1 2700,2690 r0 top
C75 "GRM1885C1H330JA01D" 0603#1 2700,2610 r0 top
C76 "GRM1885C1H330JA01D" 0603#1 2130,2650 r180 top
C77 "C2012X7R1A106M125AC" 0805_145 2000,3055 r270 top
C78 "06035C104KAT2A" 0603#1 1880,3305 r180 top
C79 "06035C104KAT2A" 0603#1 2180,3840 r90 top
C80 "06035C104KAT2A" 0603#1 900,2540 r270 top
C81 "GRM21BR71A225KA01L" 0805_HV 2552,3065 r270 top
C82 "06035C104KAT2A" 0603#1 2200,3090 r270 top
C83 "GRM21BR71A225KA01L" 0805_HV 2110,3060 r270 top
C84 "06035C104KAT2A" 0603#1 2750,3450 r0 top
C85 "GRM21BR71A225KA01L" 0805_HV 2780,3550 r0 top
C86 "06035C104KAT2A" 0603#1 1730,5930 r180 top
C87 "GRM188R72A104KA35D" 0603#1 1880,5930 r0 top
C88 "GRM188R72A104KA35D" 0603#1 1800,6865 r180 top
C89 "06035C104KAT2A" 0603#1 900,6550 r270 top
C90 "06035C104KAT2A" 0603#1 1730,5850 r180 top
C91 "GRM188R72A104KA35D" 0603#1 1880,5850 r0 top
C92 "06035C104KAT2A" 0603#1 900,6200 r270 top
C93 "06035C104KAT2A" 0603#1 1730,5770 r180 top
C94 "GRM188R72A104KA35D" 0603#1 1880,5770 r0 top
C95 "06035C104KAT2A" 0603#1 900,5850 r270 top
C96 "GRM188R71C473KA01D" 0603#1 2289,5130 r90 top
C97 "GRM188R71C473KA01D" 0603#1 2220,6260 r270 top
C98 "06035C104KAT2A" 0603#1 1730,5690 r180 top
C99 "GRM188R72A104KA35D" 0603#1 1880,5690 r0 top
C100 "06035C104KAT2A" 0603#1 900,5500 r270 top
C101 "06035C104KAT2A" 0603#1 1730,5610 r180 top
C102 "GRM188R72A104KA35D" 0603#1 1880,5610 r0 top
C103 "GRM188R72A104KA35D" 0603#1 900,5150 r270 top
C104 "C0603C104K4RACTU" 0603#1 2830,5890 r0 top
C105 "C0603C104K4RACTU" 0603#1 2830,6130 r0 top
C106 "C0603C104K4RACTU" 0603#1 2710,5980 r270 top
C107 "06035C104KAT2A" 0603#1 1880,5530 r180 top
C108 "GRM1885C1H330JA01D" 0603#1 2200,4965 r180 top
C109 "GRM1885C1H330JA01D" 0603#1 2640,5120 r0 top
C110 "GRM1885C1H330JA01D" 0603#1 2640,5040 r0 top
C111 "GRM1885C1H330JA01D" 0603#1 2200,4885 r180 top
C112 "C2012X7R1A106M125AC" 0805_145 1980,5300 r270 top
C113 "06035C104KAT2A" 0603#1 900,4800 r270 top
C114 "06035C104KAT2A" 0603#1 1825,6220 r90 top
C115 "GRM21BR71A225KA01L" 0805_HV 2550,5320 r270 top
C116 "06035C104KAT2A" 0603#1 2180,5330 r270 top
C117 "GRM21BR71A225KA01L" 0805_HV 2090,5300 r270 top
C118 "06035C104KAT2A" 0603#1 2750,5700 r0 top
C119 "GRM21BR71A225KA01L" 0805_HV 2780,5800 r0 top
C120 "06035C104KAT2A" 0603#1 3475,2125 r90 top
C121 "06035C104KAT2A" 0603#1 4305,1565 r0 top
C122 "06035C104KAT2A" 0603#1 4625,1925 r270 top
C123 "06035C104KAT2A" 0603#1 3650,1575 r180 top
C124 "06035C104KAT2A" 0603#1 4300,2526 r180 top
C125 "06035C104KAT2A" 0603#1 4325,1124 r180 top
C126 "C2012X7R1A106M125AC" 0805_145 4325,1450 r0 top
C127 "C1608X7R1C105K" 0603#1 4600,350 r270 top
C128 "C0603C475K8PACTU" 0603#1 4600,675 r90 top
C129 "06035C104KAT2A" 0603#1 4500,1150 r90 top
C130 "C0603C475K8PACTU" 0603#1 3526,1025 r90 top
C131 "C0603C475K8PACTU" 0603#1 3750,800 r90 top
C132 "06035C104KAT2A" 0603#1 3650,799 r90 top
C133 "06035C104KAT2A" 0603#1 4425,525 r0 top
C134 "C0603C475K8PACTU" 0603#1 4425,450 r0 top
C135 "C2012X7R1A106M125AC" 0805_145 3775,2400 r180 top
C136 "C0603C151J5GACTU" 0603#1 4100,825 r270 top
C137 "DEBE33F102ZC3B" CAPRD750W60D700H1000 4071,186 r180 top locked
"CAUTION 1" "DANGER HIGH VOLTAGE" IEC_HighVoltage_Small 452,6488 r0 top
D1 "APT1608SYCK" APT1608_Yellow 3065,680 r0 top
D2 "APT1608SYCK" APT1608_Yellow 3055,2840 r0 top
D3 "APT1608SYCK" APT1608_Yellow 3055,5120 r0 top
D4 "CSD25310Q2" TRANS_NexFET_Q2 3574.53,2123.54 r90 top
D5 "BAT54HT1G" sod-323 3697,345 r180 top
D6 "BAT54HT1G" sod-323 3697,549 r180 top
FID1 "Fiducial" Fiducial10-20#1 4835,6465 r0 top
FID2 "Fiducial" Fiducial10-20#2 365,420 r0 top
FID3 "Fiducial" Fiducial10-20#3 4831,417 r0 top
H1 "9030" Keystone_9030 191.29,6810.08 r180 bottom locked
H2 "9030" Keystone_9030 4828.51,6827.7 r180 bottom
H3 "9030" Keystone_9030 4809.63,195.37 r180 bottom
H4 "9030" Keystone_9030 190.84,190.04 r180 bottom locked
J1 "PEC02SAAN" CONN_PEC02SAAN 503,1935 r0 top
J2 "PEC02SAAN" CONN_PEC02SAAN 4447,4409 r90 top
J3 "PEC02SAAN" CONN_PEC02SAAN 4298,4409 r90 top
J4 "PEC02SAAN" CONN_PEC02SAAN 511,4080 r0 top
J5 "PEC02SAAN" CONN_PEC02SAAN 4425,5321 r90 top
J6 "PEC02SAAN" CONN_PEC02SAAN 4300,5322 r90 top
J7 "PEC02SAAN" CONN_PEC02SAAN 510,5855 r0 top
J8 "PEC02SAAN" CONN_PEC02SAAN 4426,6258 r90 top
J9 "PEC02SAAN" CONN_PEC02SAAN 4297,6259 r90 top
JP1 "PEC02SAAN" CONN_PEC02SAAN 504,5598 r0 top
JP2 "PEC02SAAN" CONN_PEC02SAAN 504,5448 r0 top
JP3 "PEC02SAAN" CONN_PEC02SAAN 504,5298 r0 top
JP4 "PEC02SAAN" CONN_PEC02SAAN 504,5148 r0 top
JP5 "PEC02SAAN" CONN_PEC02SAAN 504,4998 r0 top
JP6 "PEC02SAAN" CONN_PEC02SAAN 504,4848 r0 top
JP7 "PEC02SAAN" CONN_PEC02SAAN 504,3854 r0 top
JP8 "PEC02SAAN" CONN_PEC02SAAN 504,3704 r0 top
JP9 "PEC02SAAN" CONN_PEC02SAAN 504,3554 r0 top
JP10 "PEC02SAAN" CONN_PEC02SAAN 504,3404 r0 top
JP11 "PEC02SAAN" CONN_PEC02SAAN 504,3254 r0 top
JP12 "PEC02SAAN" CONN_PEC02SAAN 504,3104 r0 top
JP13 "PEC02SAAN" CONN_PEC02SAAN 504,1740 r0 top
JP14 "PEC02SAAN" CONN_PEC02SAAN 504,1590 r0 top
JP15 "PEC02SAAN" CONN_PEC02SAAN 504,1440 r0 top
JP16 "PEC02SAAN" CONN_PEC02SAAN 504,1290 r0 top
JP17 "PEC02SAAN" CONN_PEC02SAAN 504,1140 r0 top
JP18 "PEC02SAAN" CONN_PEC02SAAN 504,990 r0 top
JP19 "PEC03SAAN" CONN_PEC03SAAN 4177,1325 r270 top
L1 "LB2012T100KR" 0805_HV 3525,825 r90 top
LBL1 "Size: 0.65\" x 0.20 \"" Label_650x200 3781.16,4866.06 r90 top
Logo1 "Texas Instruments" TI_Stacked_Overlay_Small 4003,6775 r0 top
Logo2 "Pb-Free Symbol" Pb-Free_Overlay_Small 4891,4473 r0 top
Logo3 "FCC disclaimer" FCC_disclaimer 4893,5245 r90 top
P1 "395021007" Molex_395021007 200,1451.61 r270 top locked
P2 "395021007" Molex_395021007 200,3496 r270 top locked
P3 "395021007" Molex_395021007 200,5236.61 r270 top locked
P4 "5103308-1" CONN_5103308-1 2500,6790 r0 top locked
P5 "5103308-1" CONN_5103308-1 4800,1225 r270 top locked
P6 "HPM-10-05-T-S" Samtec_HPM-10-05-T-S 4802.59,2652.75 r90 top
P7 "5103308-1" CONN_5103308-1 3230,1550 r270 top locked
P8 "5103308-1" CONN_5103308-1 2495,190 r0 top locked
Q1 "CSD16301Q2" TRANS_NexFET_Q2 1455,2124 r90 top
Q2 "CSD16301Q2" TRANS_NexFET_Q2 3100,975 r90 top
Q3 "CSD16301Q2" TRANS_NexFET_Q2 1455,1750 r90 top
Q4 "CSD16301Q2" TRANS_NexFET_Q2 1455,1400 r90 top
Q5 "CSD16301Q2" TRANS_NexFET_Q2 3070,805 r270 top
Q6 "CSD16301Q2" TRANS_NexFET_Q2 1455,1050 r90 top
Q7 "CSD16301Q2" TRANS_NexFET_Q2 1455,700 r90 top
Q8 "CSD16301Q2" TRANS_NexFET_Q2 1455,322 r90 top
Q9 "CSD16301Q2" TRANS_NexFET_Q2 1455,4395 r90 top
Q10 "CSD16301Q2" TRANS_NexFET_Q2 1455,4076 r90 top
Q11 "CSD16301Q2" TRANS_NexFET_Q2 1455,3725 r90 top
Q12 "CSD16301Q2" TRANS_NexFET_Q2 3065,2954 r270 top
Q13 "CSD16301Q2" TRANS_NexFET_Q2 1455,3375 r90 top
Q14 "CSD16301Q2" TRANS_NexFET_Q2 1455,3000 r90 top
Q15 "CSD16301Q2" TRANS_NexFET_Q2 1455,2595 r90 top
Q16 "CSD16301Q2" TRANS_NexFET_Q2 1455,6689 r90 top
Q17 "CSD16301Q2" TRANS_NexFET_Q2 1455,6340 r90 top
Q18 "CSD16301Q2" TRANS_NexFET_Q2 1455,5990 r90 top
Q19 "CSD16301Q2" TRANS_NexFET_Q2 1455,5639 r90 top
Q20 "CSD16301Q2" TRANS_NexFET_Q2 3065,5240 r270 top
Q21 "CSD16301Q2" TRANS_NexFET_Q2 1455,5295 r90 top
Q22 "CSD16301Q2" TRANS_NexFET_Q2 1455,4944 r90 top
Q23 "CSD16301Q2" TRANS_NexFET_Q2 4375,325 r90 top
Q24 "CSD16301Q2" TRANS_NexFET_Q2 4375,650 r90 top
R1 "CRCW12061K00FKEA" 1206 2011,6539 r90 top
R2 "CRCW06030000Z0EA" 0603#1 2100,6540 r90 top
R3 "CRCW06030000Z0EA" 0603#1 2180,6540 r90 top
R4 "CRCW06030000Z0EA" 0603#1 2260,6540 r90 top
R5 "CRCW06030000Z0EA" 0603#1 2340,6540 r90 top
R6 "CRCW06030000Z0EA" 0603#1 2420,6540 r90 top
R7 "CRCW06030000Z0EA" 0603#1 2500,6540 r90 top
R8 "CRCW06030000Z0EA" 0603#1 2580,6540 r90 top
R9 "CRCW06030000Z0EA" 0603#1 2660,6540 r90 top
R10 "CRCW12061K00FKEA" 1206 2750,6504 r90 top
R11 "CRCW12061K00FKEA" 1206 2860,6502.63 r90 top
R12 "CRCW12061K00FKEA" 1206 2972.87,6502.81 r90 top
R13 "CRCW06031K00JNEA" 0603#1 735,5600 r0 top
R14 "CRCW06031K00JNEA" 0603#1 735,5450 r0 top
R15 "CRCW06031K00JNEA" 0603#1 735,5300 r0 top
R16 "CRCW06031K00JNEA" 0603#1 735,5150 r0 top
R17 "CRCW06031K00JNEA" 0603#1 735,5000 r0 top
R18 "CRCW06031K00JNEA" 0603#1 735,4850 r0 top
R19 "CRCW12060000Z0EA" 1206 348,4779 r90 top
R20 "CRCW06030000Z0EA" 0603#1 200,4555 r90 top
R21 "RG1608P-102-B-T5" 0603#1 2420,4780 r90 top
R22 "RG1608P-102-B-T5" 0603#1 2510,4780 r90 top
R23 "RG1608P-102-B-T5" 0603#1 2597,4780 r90 top
R24 "RG1608P-102-B-T5" 0603#1 2330,4780 r90 top
R25 "RG1608P-102-B-T5" 0603#1 2300,4330 r90 top
R26 "RG1608P-102-B-T5" 0603#1 2440,4330 r90 top
R27 "RG1608P-102-B-T5" 0603#1 2525,4330 r90 top
R28 "RG1608P-102-B-T5" 0603#1 2615,4330 r90 top
R29 "CRCW12060000Z0EA" 1206 2030,4535 r90 top
R30 "CRCW06031K00JNEA" 0603#1 735,3855 r0 top
R31 "CRCW06031K00JNEA" 0603#1 735,3705 r0 top
R32 "CRCW06031K00JNEA" 0603#1 735,3555 r0 top
R33 "CRCW06031K00JNEA" 0603#1 735,3405 r0 top
R34 "CRCW06031K00JNEA" 0603#1 735,3255 r0 top
R35 "CRCW06031K00JNEA" 0603#1 735,3105 r0 top
R36 "CRCW12060000Z0EA" 1206 323.01,3031.18 r90 top
R37 "CRCW06030000Z0EA" 0603#1 205,2280 r90 top
R38 "RG1608P-102-B-T5" 0603#1 2260,2520 r90 top
R39 "RG1608P-102-B-T5" 0603#1 2350,2520 r90 top
R40 "RG1608P-102-B-T5" 0603#1 2440,2520 r90 top
R41 "RG1608P-102-B-T5" 0603#1 2528,2520 r90 top
R42 "RG1608P-102-B-T5" 0603#1 2270,2140 r90 top
R43 "RG1608P-102-B-T5" 0603#1 2400,2140 r90 top
R44 "RG1608P-102-B-T5" 0603#1 2475,2140 r90 top
R45 "RG1608P-102-B-T5" 0603#1 2550,2140 r90 top
R46 "CRCW12060000Z0EA" 1206 1985,2275 r90 top
R47 "CRCW06031K00JNEA" 0603#1 735,1740 r0 top
R48 "CRCW06031K00JNEA" 0603#1 735,1590 r0 top
R49 "CRCW06031K00JNEA" 0603#1 735,1440 r0 top
R50 "CRCW06031K00JNEA" 0603#1 735,1290 r0 top
R51 "CRCW06031K00JNEA" 0603#1 735,1140 r0 top
R52 "CRCW06031K00JNEA" 0603#1 735,990 r0 top
R53 "CRCW12060000Z0EA" 1206 329.46,941.2 r90 top
R54 "CRCW12061K00FKEA" 1206 1943,474.49 r90 top
R55 "CRCW12061K00FKEA" 1206 2053,474.49 r90 top
R56 "CRCW12061K00FKEA" 1206 2163,474.49 r90 top
R57 "CRCW06030000Z0EA" 0603#1 2255,440 r90 top
R58 "CRCW06030000Z0EA" 0603#1 2330,440 r90 top
R59 "CRCW06030000Z0EA" 0603#1 2405,440 r90 top
R60 "CRCW06030000Z0EA" 0603#1 2480,440 r90 top
R61 "CRCW06030000Z0EA" 0603#1 2555,440 r90 top
R62 "CRCW06030000Z0EA" 0603#1 2630,440 r90 top
R63 "CRCW06030000Z0EA" 0603#1 2705,440 r90 top
R64 "CRCW06030000Z0EA" 0603#1 2780,440 r90 top
R65 "CRCW12061K00FKEA" 1206 2879,474.49 r90 top
R66 "CRCW251247R0JNEG" 2512 1120,2075 r180 top
R67 "RG1608P-102-B-T5" 0603#1 1720.02,2056.75 r180 top
R68 "CRCW08050000Z0EA" 0805_HV 1930,1790 r270 top
R69 "RG1608P-102-B-T5" 0603#1 1570,2000 r180 top
R70 "ERJ-3EKF1002V" 0603#1 2950,975 r180 top
R71 "CRCW06031M00JNEA" 0603#1 1436,1953 r90 top
R72 "RG1608P-102-B-T5" 0603#1 1570,1925 r180 top
R73 "RG1608P-102-B-T5" 0603#1 3340,1062 r270 top
R74 "CRCW251247R0JNEG" 2512 1120,1700 r180 top
R75 "ERJ-3EKF1002V" 0603#1 3225,940 r180 top
R76 "RG1608P-102-B-T5" 0603#1 1570,1625 r180 top
R77 "CRCW06031K60JNEA" 0603#1 2885,680 r180 top
R78 "CRCW06031M00JNEA" 0603#1 1436,1582 r90 top
R79 "RG1608P-102-B-T5" 0603#1 1570,1550 r180 top
R80 "ERJ-3EKF1002V" 0603#1 3195,1062 r270 top
R81 "CRCW251247R0JNEG" 2512 1120,1350 r180 top
R82 "ERJ-3EKF1002V" 0603#1 3270,1062 r270 top
R83 "ERJ-3EKF1002V" 0603#1 3190,2055 r90 top
R84 "CRCW06031K47FKEA" 0603#1 2315,725 r270 top
R85 "CRCW06031K47FKEA" 0603#1 2210,1850 r90 top
R86 "CRCW0603100KFKEA" 0603#1 2835,800 r270 top
R87 "RG1608P-102-B-T5" 0603#1 1570,1275 r180 top
R88 "CRCW0603100RJNEA" 0603#1 2926,800 r270 top
R89 "CRCW06031K82FKEA" 0603#1 2276,880 r270 top
R90 "CRCW06031M00JNEA" 0603#1 1435,1234 r90 top
R91 "CRCW06031K82FKEA" 0603#1 2260,1690 r90 top
R92 "RG1608P-102-B-T5" 0603#1 1570,1200 r180 top
R93 "CRCW251247R0JNEG" 2512 1120,1000 r180 top
R94 "CRCW06030000Z0EA" 0603#1 2770,970 r180 top
R95 "RG1608P-102-B-T5" 0603#1 1570,925 r180 top
R96 "CRCW06030000Z0EA" 0603#1 2770,1050 r0 top
R97 "CRCW06031M00JNEA" 0603#1 1434,882 r90 top
R98 "RG1608P-102-B-T5" 0603#1 1570,850 r180 top
R99 "CRCW06030000Z0EA" 0603#1 2940,1675 r90 top
R100 "CRCW251247R0JNEG" 2512 1120,650 r180 top
R101 "CRCW06030000Z0EA" 0603#1 2815,1630 r0 top
R102 "RG1608P-102-B-T5" 0603#1 1570,575 r180 top
R103 "CRCW06030000Z0EA" 0603#1 2720,1920 r180 top
R104 "CRCW06030000Z0EA" 0603#1 2720,2000 r180 top
R105 "CRCW06030000Z0EA" 0603#1 2720,2080 r180 top
R106 "CRCW06030000Z0EA" 0603#1 3015,1675 r90 top
R107 "CRCW06031M00JNEA" 0603#1 1434,532 r90 top
R108 "CRCW06030000Z0EA" 0603#1 2815,1555 r0 top
R109 "RG1608P-102-B-T5" 0603#1 1570,500 r180 top
R110 "CRCW251247R0JNEG" 2512 1120,300 r180 top
R111 "RG1608P-102-B-T5" 0603#1 1570,200 r180 top
R112 "CRCW06031M00JNEA" 0603#1 1435,161 r90 top
R113 "CRCW251247R0JNEG" 2512 1120,4390 r180 top
R114 "RG1608P-102-B-T5" 0603#1 1700,4330 r180 top
R115 "CRCW08050000Z0EA" 0805_HV 1927,3950 r270 top
R116 "RG1608P-102-B-T5" 0603#1 1570,4275 r180 top
R117 "CRCW06031M00JNEA" 0603#1 1435,4250 r90 top
R118 "RG1608P-102-B-T5" 0603#1 1570,4200 r180 top
R119 "CRCW251247R0JNEG" 2512 1120,4040 r180 top
R120 "RG1608P-102-B-T5" 0603#1 1570,3950 r180 top
R121 "CRCW06031M00JNEA" 0603#1 1435,3900 r90 top
R122 "RG1608P-102-B-T5" 0603#1 1570,3875 r180 top
R123 "CRCW06031K60JNEA" 0603#1 2885,2840 r180 top
R124 "CRCW251247R0JNEG" 2512 1122,3689 r180 top
R125 "RG1608P-102-B-T5" 0603#1 1565,3575 r180 top
R126 "CRCW0603100KFKEA" 0603#1 2835,2960 r270 top
R127 "CRCW06031K47FKEA" 0603#1 2240,2860 r270 top
R128 "CRCW06031K47FKEA" 0603#1 2285,4030 r90 top
R129 "CRCW06031M00JNEA" 0603#1 1435,3558 r90 top
R130 "CRCW0603100RJNEA" 0603#1 2915,2960 r90 top
R131 "RG1608P-102-B-T5" 0603#1 1565,3500 r180 top
R132 "CRCW06031K82FKEA" 0603#1 2280,3020 r270 top
R133 "CRCW251247R0JNEG" 2512 1120,3340 r180 top
R134 "CRCW06031K82FKEA" 0603#1 2260,3870 r90 top
R135 "CRCW0603100KFKEA" 0603#1 2750,3370 r0 top
R136 "RG1608P-102-B-T5" 0603#1 1570,3250 r180 top
R137 "CRCW06031M00JNEA" 0603#1 1436,3213 r90 top
R138 "RG1608P-102-B-T5" 0603#1 1570,3175 r180 top
R139 "CRCW251247R0JNEG" 2512 1120,2990 r180 top
R140 "CRCW06030000Z0EA" 0603#1 3035,3835 r90 top
R141 "CRCW06030000Z0EA" 0603#1 2830,3865 r0 top
R142 "RG1608P-102-B-T5" 0603#1 1570,2875 r180 top
R143 "CRCW06031M00JNEA" 0603#1 1435,2833 r90 top
R144 "CRCW06030000Z0EA" 0603#1 3110,3835 r90 top
R145 "RG1608P-102-B-T5" 0603#1 1570,2800 r180 top
R146 "CRCW06030000Z0EA" 0603#1 2830,3715 r0 top
R147 "CRCW251247R0JNEG" 2512 1120,2640 r180 top
R148 "RG1608P-102-B-T5" 0603#1 1570,2475 r180 top
R149 "CRCW06031M00JNEA" 0603#1 1435,2428 r90 top
R150 "CRCW251247R0JNEG" 2512 1120,6650 r180 top
R151 "RG1608P-102-B-T5" 0603#1 1725,6605 r180 top
R152 "CRCW08050000Z0EA" 0805_HV 1927,6190 r270 top
R153 "RG1608P-102-B-T5" 0603#1 1565,6555 r180 top
R154 "CRCW06031M00JNEA" 0603#1 1435,6520 r90 top
R155 "RG1608P-102-B-T5" 0603#1 1565,6485 r180 top
R156 "CRCW251247R0JNEG" 2512 1120,6300 r180 top
R157 "RG1608P-102-B-T5" 0603#1 1565,6200 r180 top
R158 "CRCW06031M00JNEA" 0603#1 1435,6165 r90 top
R159 "RG1608P-102-B-T5" 0603#1 1565,6130 r180 top
R160 "CRCW251247R0JNEG" 2512 1120,5950 r180 top
R161 "CRCW06031K60JNEA" 0603#1 2885,5120 r180 top
R162 "RG1608P-102-B-T5" 0603#1 1565,5855 r180 top
R163 "CRCW06031M00JNEA" 0603#1 1435,5820 r90 top
R164 "RG1608P-102-B-T5" 0603#1 1565,5785 r180 top
R165 "CRCW06031K47FKEA" 0603#1 2209,5130 r270 top
R166 "CRCW06031K47FKEA" 0603#1 2300,6260 r90 top
R167 "CRCW251247R0JNEG" 2512 1120,5600 r180 top
R168 "CRCW0603100KFKEA" 0603#1 2835,5240 r270 top
R169 "CRCW06031K82FKEA" 0603#1 2260,5305 r270 top
R170 "CRCW06031K82FKEA" 0603#1 2265,6100 r90 top
R171 "CRCW0603100RJNEA" 0603#1 2915,5240 r90 top
R172 "CRCW0603100KFKEA" 0603#1 2750,5620 r0 top
R173 "RG1608P-102-B-T5" 0603#1 1565,5505 r180 top
R174 "CRCW06031M00JNEA" 0603#1 1435,5470 r90 top
R175 "RG1608P-102-B-T5" 0603#1 1565,5435 r180 top
R176 "CRCW251247R0JNEG" 2512 1120,5250 r180 top
R177 "CRCW06030000Z0EA" 0603#1 2700,4955 r180 top
R178 "RG1608P-102-B-T5" 0603#1 1565,5155 r180 top
R179 "CRCW06030000Z0EA" 0603#1 3045,6100 r90 top
R180 "CRCW06031M00JNEA" 0603#1 1435,5120 r90 top
R181 "CRCW06030000Z0EA" 0603#1 2830,6050 r0 top
R182 "RG1608P-102-B-T5" 0603#1 1565,5085 r180 top
R183 "CRCW251247R0JNEG" 2512 1120,4900 r180 top
R184 "CRCW06030000Z0EA" 0603#1 3135,6100 r90 top
R185 "CRCW06030000Z0EA" 0603#1 2830,5970 r0 top
R186 "RG1608P-102-B-T5" 0603#1 1570,4810 r180 top
R187 "CRCW06031M00JNEA" 0603#1 1435,4775 r90 top
R188 "CRCW0603100RJNEA" 0603#1 3725,2300 r0 top
R189 "CRCW0603100RJNEA" 0603#1 3725,2225 r0 top
R190 "CRCW06031M00JNEA" 0603#1 4450,2474 r90 top
R191 "CRCW06031M00JNEA" 0603#1 4650,2475 r90 top
R192 "CRCW06031M00JNEA" 0603#1 4550,2475 r90 top
R193 "CRCW0603100RJNEA" 0603#1 3725,2150 r0 top
R194 "CRCW0603100RJNEA" 0603#1 3725,2075 r0 top
R195 "CRCW06031M00JNEA" 0603#1 4550,1925 r270 top
R196 "ERJ-3EKF1002V" 0603#1 3550,2000 r0 top
R197 "CRCW0603100RJNEA" 0603#1 3600,1675 r180 top
R198 "CRCW06030000Z0EA" 0603#1 4475,1625 r0 top
R199 "CRCW06030000Z0EA" 0603#1 4475,1700 r0 top
R200 "CRCW06030000Z0EA" 0603#1 4475,1775 r0 top
R201 "CRCW0603100RJNEA" 0603#1 3600,1750 r180 top
R202 "RG1608P-102-B-T5" 0603#1 3550,2250 r0 top
R203 "CRCW0603100RJNEA" 0603#1 3600,1825 r180 top
R204 "CRCW0603100KFKEA" 0603#1 4450,1925 r90 top
R205 "CRCW0603100RJNEA" 0603#1 4325,1825 r180 top
R206 "CRCW0603100RJNEA" 0603#1 3600,1900 r180 top
R207 "ERJ-3EKF1002V" 0603#1 4550,1375 r0 top
R208 "ERJ-3EKF1002V" 0603#1 4551,1450 r0 top
R209 "ERJ-3EKF1002V" 0603#1 4550,1526 r0 top
R210 "RC0603FR-072RL" 0603#1 4600,500 r270 top
R211 "ERJ-3EKF1002V" 0603#1 4100,1000 r270 top
R212 "RC0603FR-07523KL" 0603#1 3650,1175 r0 top
R213 "RC0603FR-07169KL" 0603#1 3775,1050 r90 top
R214 "RG1608P-102-B-T5" 0603#1 4350,775 r0 top
R215 "CRCW06031R00JNEA" 0603#1 4500,700 r90 top
RT1 "ERT-J1VG103FA" 0603#1 4550,4420 r90 top
RT2 "ERT-J1VG103FA" 0603#1 4200,4420 r90 top
RT3 "ERT-J1VG103FA" 0603#1 4550,5330 r90 top
RT4 "ERT-J1VG103FA" 0603#1 4175,5330 r90 top
RT5 "ERT-J1VG103FA" 0603#1 4525,6250 r90 top
RT6 "ERT-J1VG103FA" 0603#1 4200,6250 r90 top
SH-J1 "969102-0000-DA" SNT-100-BK-G 504,5598 r180 top
SH-J2 "969102-0000-DA" SNT-100-BK-G 515,5455 r180 top
SH-J3 "969102-0000-DA" SNT-100-BK-G 480,5280 r180 top
SH-J4 "969102-0000-DA" SNT-100-BK-G 504,5148 r180 top
SH-J5 "969102-0000-DA" SNT-100-BK-G 504,4998 r180 top
SH-J6 "969102-0000-DA" SNT-100-BK-G 500.88,4833.77 r180 top
SH-J7 "969102-0000-DA" SNT-100-BK-G 504,3854 r180 top
SH-J8 "969102-0000-DA" SNT-100-BK-G 515,3705 r180 top
SH-JP1 "969102-0000-DA" SNT-100-BK-G 4295,6265 r90 top
SH-JP2 "969102-0000-DA" SNT-100-BK-G 515,1935 r180 top
SH-JP3 "969102-0000-DA" SNT-100-BK-G 4445,6235 r90 top
SH-JP4 "969102-0000-DA" SNT-100-BK-G 4455,4405 r90 top
SH-JP5 "969102-0000-DA" SNT-100-BK-G 4300,5320 r90 top
SH-JP6 "969102-0000-DA" SNT-100-BK-G 4295,4410 r90 top
SH-JP7 "969102-0000-DA" SNT-100-BK-G 515,5855 r180 top
SH-JP8 "969102-0000-DA" SNT-100-BK-G 525,4075 r180 top
SH-JP9 "969102-0000-DA" SNT-100-BK-G 4425,5320 r90 top
SH-JP10 "969102-0000-DA" SNT-100-BK-G 504,3404 r180 top
SH-JP11 "969102-0000-DA" SNT-100-BK-G 504,3254 r180 top
SH-JP12 "969102-0000-DA" SNT-100-BK-G 504,3104 r180 top
SH-JP13 "969102-0000-DA" SNT-100-BK-G 504,1740 r180 top
SH-JP14 "969102-0000-DA" SNT-100-BK-G 515,1595 r180 top
SH-JP15 "969102-0000-DA" SNT-100-BK-G 504,1440 r180 top
SH-JP16 "969102-0000-DA" SNT-100-BK-G 505,1300 r180 top
SH-JP17 "969102-0000-DA" SNT-100-BK-G 504,1140 r180 top
SH-JP18 "969102-0000-DA" SNT-100-BK-G 500,985 r180 top
SH-JP19 "969102-0000-DA" SNT-100-BK-G 504,3554 r180 top
T1 "Q4470-CLB" Coilcraft_Q4470-CL 4059,501 r180 top
TP1 "5015" Testpoint_Keystone_Miniature 525,6000 r0 top
TP2 "5015" Testpoint_Keystone_Miniature 525,4680 r0 top
TP3 "5015" Testpoint_Keystone_Miniature 525,4235 r0 top
TP4 "5015" Testpoint_Keystone_Miniature 525,2875 r0 top
TP5 "5015" Testpoint_Keystone_Miniature 525,2075 r0 top
TP6 "5015" Testpoint_Keystone_Miniature 525,790 r0 top
TP-1 "5015" Testpoint_Keystone_Miniature 2100,1880 r0 top
TP-2 "5015" Testpoint_Keystone_Miniature 1910,710 r0 top
TP-3 "5015" Testpoint_Keystone_Miniature 2077,710 r0 top
TP-4 "5015" Testpoint_Keystone_Miniature 2100,2020 r0 top
TP-5 "5015" Testpoint_Keystone_Miniature 2935,2140 r0 top
TP-6 "5015" Testpoint_Keystone_Miniature 2937.44,2002.02 r0 top
TP-7 "5015" Testpoint_Keystone_Miniature 2040,4115 r0 top
TP-8 "5015" Testpoint_Keystone_Miniature 2070,2765 r0 top
TP-9 "5015" Testpoint_Keystone_Miniature 2070,2905 r0 top
TP-10 "5015" Testpoint_Keystone_Miniature 2040,4260 r0 top
TP-11 "5015" Testpoint_Keystone_Miniature 3005,4010 r0 top
TP-12 "5015" Testpoint_Keystone_Miniature 3178,4010 r0 top
TP-13 "5015" Testpoint_Keystone_Miniature 1930.75,6355 r0 top
TP-14 "5015" Testpoint_Keystone_Miniature 1975,4925 r0 top
TP-15 "5015" Testpoint_Keystone_Miniature 1975,5075 r0 top
TP-16 "5015" Testpoint_Keystone_Miniature 2100,6355 r0 top
TP-17 "5015" Testpoint_Keystone_Miniature 3015,6280 r0 top
TP-18 "5015" Testpoint_Keystone_Miniature 3185,6280 r0 top
TP-19 "5015" Testpoint_Keystone_Miniature 4550,2710 r0 top
TP-20 "5020" Testpoint_Keystone_Miniature 3725,1380 r0 top
TP-AGN "5015" Testpoint_Keystone_Miniature 4425,150 r0 top
TP-C1 "5015" Testpoint_Keystone_Miniature 1640,2165 r0 top
TP-C2 "5015" Testpoint_Keystone_Miniature 1815,2165 r0 top
TP-C3 "5015" Testpoint_Keystone_Miniature 1640,4435 r0 top
TP-C4 "5015" Testpoint_Keystone_Miniature 1810,4435 r0 top
TP-C5 "5015" Testpoint_Keystone_Miniature 1620,6755 r0 top
TP-C6 "5015" Testpoint_Keystone_Miniature 1790,6755 r0 top
TP-SW1 "5015" Testpoint_Keystone_Miniature 4825,640 r0 top
TP-VPROG1 "5015" Testpoint_Keystone_Miniature 2960,1460 r90 top
TP-VPROG2 "5015" Testpoint_Keystone_Miniature 3050,3450 r0 top
TP-VPROG3 "5015" Testpoint_Keystone_Miniature 3050,5700 r0 top
TP-VSS1 "5015" Testpoint_Keystone_Miniature 3280,760 r0 top
TP-VSS2 "5015" Testpoint_Keystone_Miniature 3050,5560 r0 top
TP-VSS3 "5015" Testpoint_Keystone_Miniature 3595,130 r0 top
TPTP-VSS1 "5015" Testpoint_Keystone_Miniature 3050,3305 r180 top
U1 "BQ76PL536APAPR" PAP0064F_N 2350,1280 r0 top locked
U2 "BQ76PL536APAPR" PAP0064F_N 2350,3450 r0 top locked
U3 "BQ76PL536APAPR" PAP0064F_N 2350,5700 r0 top locked
U4 "ISO7241CDW" DW0016A_N 4125,2225 r0 top locked
U5 "PCA9557PWR" PW0016A_N 4550,2200 r270 top locked
U6 "ISO7241CDW" DW0016A_N 3975,1750 r180 top locked
U7 "TPS76933DBVR" DBV0005A_N 4325,1300 r90 top
U8 "UCC2808DTR-2" D0008A_N 4350,950 r0 top
U9 "TPS76901DBV" DBV0005A_N 3650,1050 r90 top
Z1 "SMAJ36CA" SMA 1820,1820 r270 top
Z2 "MMSZ5232B-7-F" SOD-123 1131,1913 r180 top
Z3 "MMSZ5232B-7-F" SOD-123 1343,1950 r270 top
Z4 "MMSZ5232B-7-F" SOD-123 1131,1542 r180 top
